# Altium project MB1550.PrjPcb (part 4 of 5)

## Sheet PMOD_STMOD+.SchDoc: PMOD & STMOD+
size A4; Date: Not used; ApprovedBy: Not used; CheckedBy: Not used; Author: Not used; CompanyName: STMicroelectronics; DrawnBy: Not used; Engineer: Not used; Organization: Not used; Address1: Not used; Address2: Not used; Address3: Not used; Address4: Not used; DocumentNumber: 19; Revision: Not used; SheetNumber: 19; SheetTotal: 24
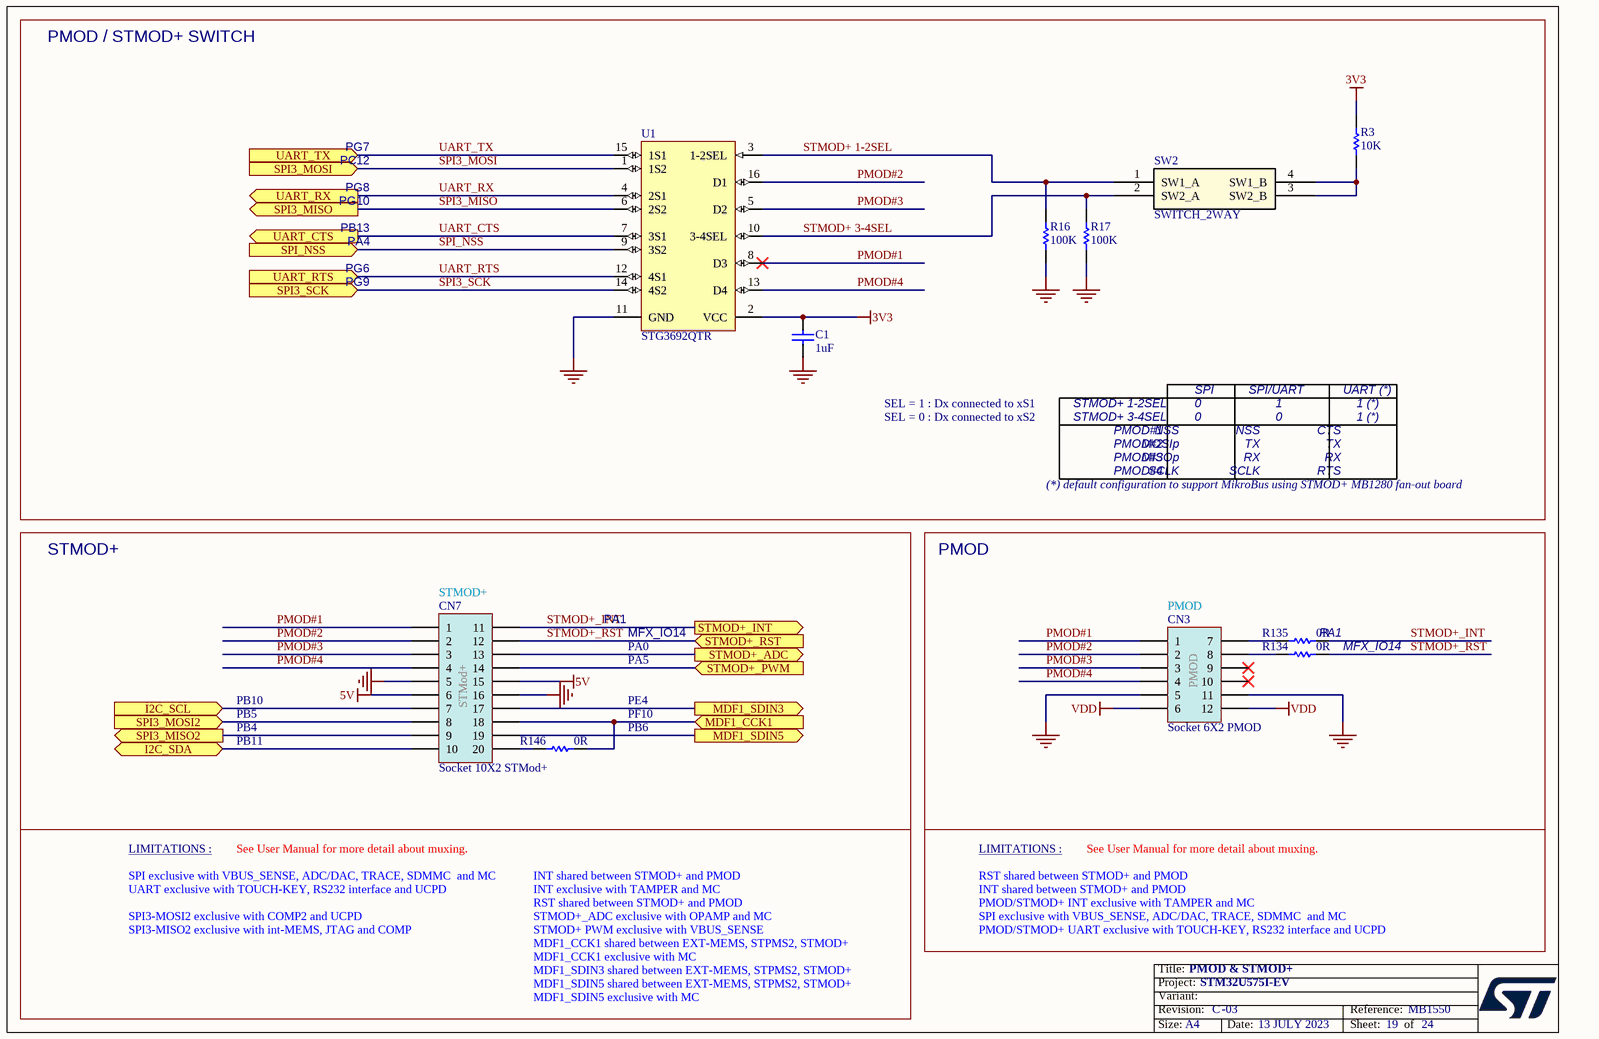
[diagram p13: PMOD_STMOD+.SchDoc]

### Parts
C1  value 1uF  [C0603]  (hidden comment: Capacitor)
CN3  Socket 6X2 PMOD  [CON_SAMTEC_SSW-106-02-F-D-RA__PMOD]
CN7  Socket 10X2 STMod+  [CON_SAMTEC_SQT-110-01-F-D-RA__STMOD+]
R3  value 10K  [R0603]  (hidden comment: Resistor)
R16  value 100K  [R0603]
R17  value 100K  [R0603]
R134  value 0R  [R0603]
R135  value 0R  [R0603]
R146  value 0R  [R0603]
SW2  SWITCH_2WAY  [SWI_C&K_SDA02H1SBD_2POS]
U1  STG3692QTR  [ICC_UFQFN16-EPAD_2P6X1P8_P040]

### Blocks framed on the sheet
PMOD / STMOD+ SWITCH: C1 R3 R16 R17 SW2 U1
STMOD+: CN7 R146
PMOD: CN3 R134 R135

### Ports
I2C_SCL (in), I2C_SDA (bidir), MDF1_CCK1 (in), MDF1_SDIN3 (out), MDF1_SDIN5 (out), SPI3_MISO2 (out), SPI3_MISO (out), SPI3_MOSI2 (in), SPI3_MOSI (in), SPI3_SCK (in), SPI_NSS (in), STMOD+_ADC (out), STMOD+_INT (out), STMOD+_PWM (in), STMOD+_RST (in), UART_CTS (out), UART_RTS (in), UART_RX (out), UART_TX (in)

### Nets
3V3: C1.2 R3.2 U1.2(VCC)
5V: CN7.6 CN7.15
GND: C1.1 CN3.5 CN3.11 CN7.5 CN7.16 R16.1 R17.1 U1.11(GND)
VDD: CN3.6 CN3.12
I2C_SCL: CN7.7 ; port I2C_SCL
I2C_SDA: CN7.10 ; port I2C_SDA
MDF1_CCK1: CN7.18 R146.1 ; port MDF1_CCK1
MDF1_SDIN3: CN7.17 ; port MDF1_SDIN3
MDF1_SDIN5: CN7.19 ; port MDF1_SDIN5
PMOD#1: CN3.1 CN7.1 U1.8(D3)
PMOD#2: CN3.2 CN7.2 U1.16(D1)
PMOD#3: CN3.3 CN7.3 U1.5(D2)
PMOD#4: CN3.4 CN7.4 U1.13(D4)
SPI3_MISO: U1.6(2S2) ; port SPI3_MISO
SPI3_MISO2: CN7.9 ; port SPI3_MISO2
SPI3_MOSI: U1.1(1S2) ; port SPI3_MOSI
SPI3_MOSI2: CN7.8 ; port SPI3_MOSI2
SPI3_SCK: U1.14(4S2) ; port SPI3_SCK
SPI_NSS: U1.9(3S2) ; port SPI_NSS
STMOD+ 1-2SEL: R16.2 SW2.1(SW1_A) U1.3(1-2SEL)
STMOD+ 3-4SEL: R17.2 SW2.2(SW2_A) U1.10(3-4SEL)
STMOD+_ADC: CN7.13 ; port STMOD+_ADC
STMOD+_INT: CN7.11 R135.2 ; port STMOD+_INT
STMOD+_PWM: CN7.14 ; port STMOD+_PWM
STMOD+_RST: CN7.12 R134.2 ; port STMOD+_RST
UART_CTS: U1.7(3S1) ; port UART_CTS
UART_RTS: U1.12(4S1) ; port UART_RTS
UART_RX: U1.4(2S1) ; port UART_RX
UART_TX: U1.15(1S1) ; port UART_TX
NetCN3_7: CN3.7 R135.1
NetCN3_8: CN3.8 R134.1
NetCN7_20: CN7.20 R146.2
NetR3_1: R3.1 SW2.3(SW2_B) SW2.4(SW1_B)

Not connected (* = marked no-connect by the designer): CN3 9* 10*

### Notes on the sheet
- PG7
- PC12
- PB13
- PG8
- PG10
- PA4
- PG9
- PG6
- SEL = 0 : Dx connected to xS2
- SEL = 1 : Dx connected to xS1
- STMOD+ 1-2SEL
- STMOD+ 3-4SEL
- PMOD#2
- PMOD#1
- MOSIp
- NSS
- 0
- SPI
- SPI/UART
- TX
- 1
- UART (*)
- CTS
- 1 (*)
- (*) default configuration to support MikroBus using STMOD+ MB1280 fan-out board
- PMOD#3
- PMOD#4
- MISOp
- SCLK
- RX
- RTS
- (near CN7) STMOD+
- PA0
- MFX_IO14
- PA1
- (near CN3) PMOD
- PB10
- PB5
- PA5
- PE4
- PF10
- PB11
- PB4
- PB6
- LIMITATIONS :
- See User Manual for more detail about muxing.
- SPI3-MOSI2 exclusive with COMP2 and UCPD
- UART exclusive with TOUCH-KEY, RS232 interface and UCPD
- SPI exclusive with VBUS_SENSE, ADC/DAC, TRACE, SDMMC  and MC
- RST shared between STMOD+ and PMOD
- INT shared between STMOD+ and PMOD
- INT exclusive with TAMPER and MC
- STMOD+_ADC exclusive with OPAMP and MC
- PMOD/STMOD+ INT exclusive with TAMPER and MC
- SPI3-MISO2 exclusive with int-MEMS, JTAG and COMP
- MDF1_CCK1 shared between EXT-MEMS, STPMS2, STMOD+
- MDF1_CCK1 exclusive with MC
- MDF1_SDIN3 shared between EXT-MEMS, STPMS2, STMOD+
- MDF1_SDIN5 shared between EXT-MEMS, STPMS2, STMOD+
- STMOD+ PWM exclusive with VBUS_SENSE
- PMOD/STMOD+ UART exclusive with TOUCH-KEY, RS232 interface and UCPD
- MDF1_SDIN5 exclusive with MC

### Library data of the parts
C1 = MCD-00010: Capacitor, MLCC, 1uF, 16V, X5R, 10%, 0603, T=0,8mm; Manufacturer_Part_Number: CC0603KRX5R7BB105; Manufacturer: YAGEO; Provided_By: SUBCO; Initial_Board_Reference: MB1274; Item Type: Item; Path: ws/MCD_ApplicationBoards/Lists/MCDPARTSdatabase
CN3 = MCD-00308: Socket, 6x2, 2.54mm, TH, RA, Height 8.51mm/7.62mm; Part_Type: Connector; Manufacturer_Part_Number: SSW-106-02-F-D-RA; Manufacturer: SAMTEC; Provided_By: SUBCO
CN7 = MCD-00309: Socket 10x2, 2.00mm, RA, TH, Height 6.35mm/2.29mm; Part_Type: Connector; Manufacturer_Part_Number: SQT-110-01-F-D-RA; Manufacturer: SAMTEC; Alternate_Manufacturer_Part_Number: FH200020C-12300;CNT-F200-2*10-GD-635/2.3; Alternate_Manufacturer: JIUBABA;CONNECT; Provided_By: SUBCO
R3 = MCD-00220: Resistor,10K,0603,1%,1/10W; Manufacturer_Part_Number: RC0603FR-0710KL; Manufacturer: YAGEO; Provided_By: SUBCO
R16 R17 = MCD-00223: Resistor,100K,0603,1%,1/10W; Manufacturer_Part_Number: RC0603FR-07100KL; Manufacturer: YAGEO; Provided_By: Subcon; Initial_Board_Reference: MB1319
R134 R135 R146 = MCD-00056: Resistor,0R,0603,5%,1/10W; Manufacturer_Part_Number: RC0603JR-070RL; Manufacturer: YAGEO; Provided_By: subcon; Initial_Board_Reference: MB1274
SW2 = MCD-00658: Dip Switch ,2Position ,Surface Mount Slide (Standard) ,2.54 pitch,25mA 24VDC; Part_Type: Misc; Manufacturer_Part_Number: SDA02H1SBD; Manufacturer: C&K; Provided_By: SUBCO
U1 = MCD-00317: Low voltage high bandwidth quad SPDT switch; Part_Type: IC; Manufacturer: STMICROELECTRONICS; BMS_Part_Number: 9159018; ECCN_US: EAR99; ECCN_EU: NEC; Provided_By: SUBCO with ST control

## Sheet SDCARD.SchDoc: SDCARD
size A4; Date: Not used; ApprovedBy: Not used; CheckedBy: Not used; Author: Not used; CompanyName: STMicroelectronics; DrawnBy: Not used; Engineer: Not used; Organization: Not used; Address1: Not used; Address2: Not used; Address3: Not used; Address4: Not used; DocumentNumber: 10; Revision: Not used; SheetNumber: 10; SheetTotal: 24
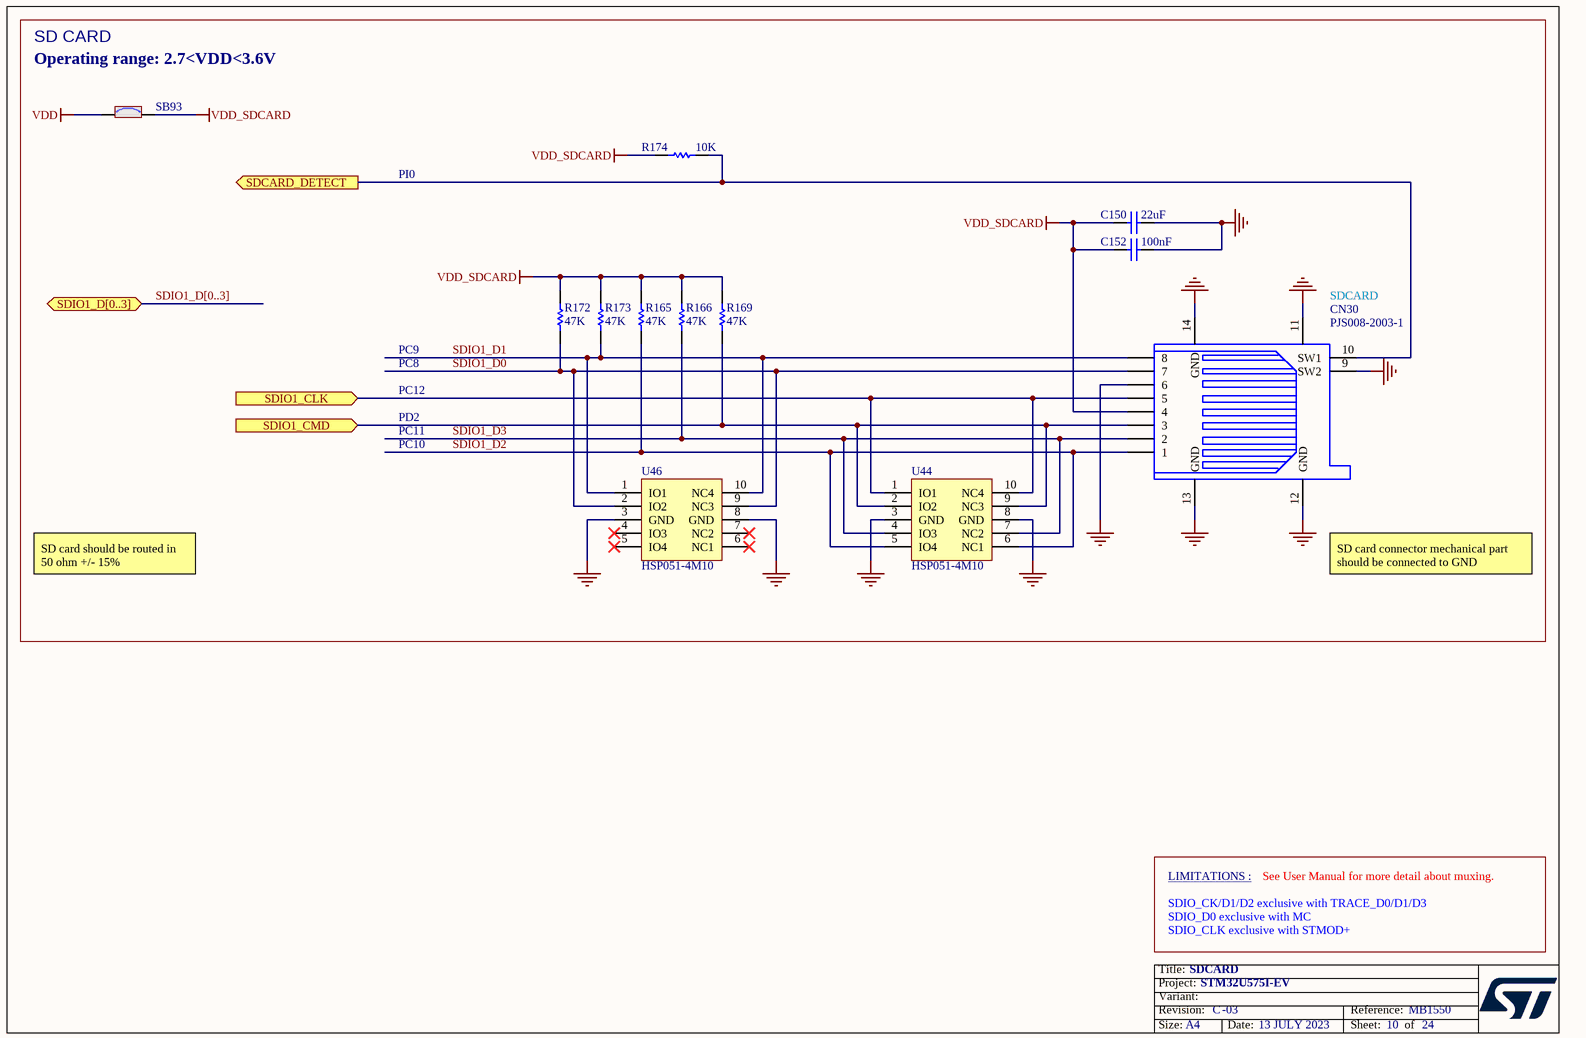
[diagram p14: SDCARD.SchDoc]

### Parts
C150  value 22uF  [C0603]
C152  value 100nF  [C0402]
CN30  value PJS008-2003-1  [CON_MICROSD_YAMAICHI_PJS008-2003-1]
R165  value 47K  [R0603]
R166  value 47K  [R0603]
R169  value 47K  [R0603]
R172  value 47K  [R0603]
R173  value 47K  [R0603]
R174  value 10K  [R0603]
SB93  (no value)  [SOLDER-BRIDGE_R0603-0R]
U44  value HSP051-4M10  [ESD_UQFN-10L_2P5X1_P050]
U46  value HSP051-4M10  [ESD_UQFN-10L_2P5X1_P050]

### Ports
SDCARD_DETECT (out), SDIO1_CLK (in), SDIO1_CMD (in), SDIO1_D[0..3] (bidir)

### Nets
GND: C150.2 C152.1 CN30.6 CN30.9(SW2) CN30.11(GND) CN30.12(GND) CN30.13(GND) CN30.14(GND) U44.3(GND) U44.8(GND) U46.3(GND) U46.8(GND)
VDD: SB93.1
VDD_SDCARD: C150.1 C152.2 CN30.4 R165.2 R166.2 R169.2 R172.2 R173.2 R174.2 SB93.2
SDCARD_DETECT: CN30.10(SW1) R174.1 ; port SDCARD_DETECT
SDIO1_CLK: CN30.5 U44.1(IO1) U44.10(NC4) ; port SDIO1_CLK
SDIO1_CMD: CN30.3 R169.1 U44.2(IO2) U44.9(NC3) ; port SDIO1_CMD
SDIO1_D0: CN30.7 R172.1 U46.2(IO2) U46.9(NC3)
SDIO1_D1: CN30.8 R173.1 U46.1(IO1) U46.10(NC4)
SDIO1_D2: CN30.1 R165.1 U44.5(IO4) U44.6(NC1)
SDIO1_D3: CN30.2 R166.1 U44.4(IO3) U44.7(NC2)

Not connected (* = marked no-connect by the designer): U46 4(IO3)* 5(IO4)* 6(NC1)* 7(NC2)*

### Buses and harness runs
bus SDIO1_D[0..3] = port SDIO1_D[0..3]

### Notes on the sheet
- SD CARD
- (near SB93) Operating range: 2.7<VDD<3.6V
- PI0
- (near CN30) SDCARD
- PC8
- PC9
- PC10
- PC11
- PD2
- PC12
- SD card should be routed in 50 ohm +/- 15%
- SD card connector mechanical part should be connected to GND
- LIMITATIONS :
- SDIO_CK/D1/D2 exclusive with TRACE_D0/D1/D3
- SDIO_D0 exclusive with MC
- See User Manual for more detail about muxing.
- SDIO_CLK exclusive with STMOD+

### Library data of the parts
C150 = MCD-00100: Capacitor, MLCC, 22uF, 6V3, X5R, 20%, 0603, T=0,8mm; Manufacturer_Part_Number: GRM188R60J226MEA0J; Manufacturer: MURATA; ECCN_US: EAR99; ECCN_EU: NEC; Provided_By: SUBCO
C152 = MCD-00006: Capacitor, MLCC, 100nF, 16V, X7R, 10%, 0402, T=0.5mm; Manufacturer_Part_Number: CC0402KRX7R7BB104; Manufacturer: YAGEO; Alternate_Manufacturer_Part_Number: GCM155R71C104KA55D; Alternate_Manufacturer: MURATA; Provided_By: SUBCO; ECCN_US: EAR99; ECCN_EU: NEC
CN30 = MCD-00023: MicroSD Card Conn, Reversed-Type, Mnt Push-Push, Positionning holes; Manufacturer: YAMAICHI; Part_Type: Connector; Provided_By: Subcon; Initial_Board_Reference: MB1274
R165 R166 R169 R172 R173 = MCD-00222: Resistor,47K,0603,1%,1/10W; Manufacturer_Part_Number: RC0603FR-0747KL; Manufacturer: YAGEO; Provided_By: Subcon; Initial_Board_Reference: MB1319
R174 = MCD-00220: Resistor,10K,0603,1%,1/10W; Manufacturer_Part_Number: RC0603FR-0710KL; Manufacturer: YAGEO; Provided_By: Subcon; Initial_Board_Reference: MB1319
SB93 = MCD-00071: Solder Bridge ON; Part_Type: Mechanical; Provided_By: Subcon; Initial_Board_Reference: MB1274
U44 U46 = MCD-00667: 4-line ESD protection for high speed lines; Part_Type: Diode; Manufacturer: STMICROELECTRONICS; BMS_Part_Number: 9179041; ECCN_US: EAR99; ECCN_EU: NEC; Provided_By: SUBCO with ST control

## Sheet SMARTCARD.SchDoc: SMARTCARD
size A4; Date: Not used; ApprovedBy: Not used; CheckedBy: Not used; Author: Not used; CompanyName: STMicroelectronics; DrawnBy: Not used; Engineer: Not used; Organization: Not used; Address1: Not used; Address2: Not used; Address3: Not used; Address4: Not used; DocumentNumber: 13; Revision: Not used; SheetNumber: 13; SheetTotal: 24
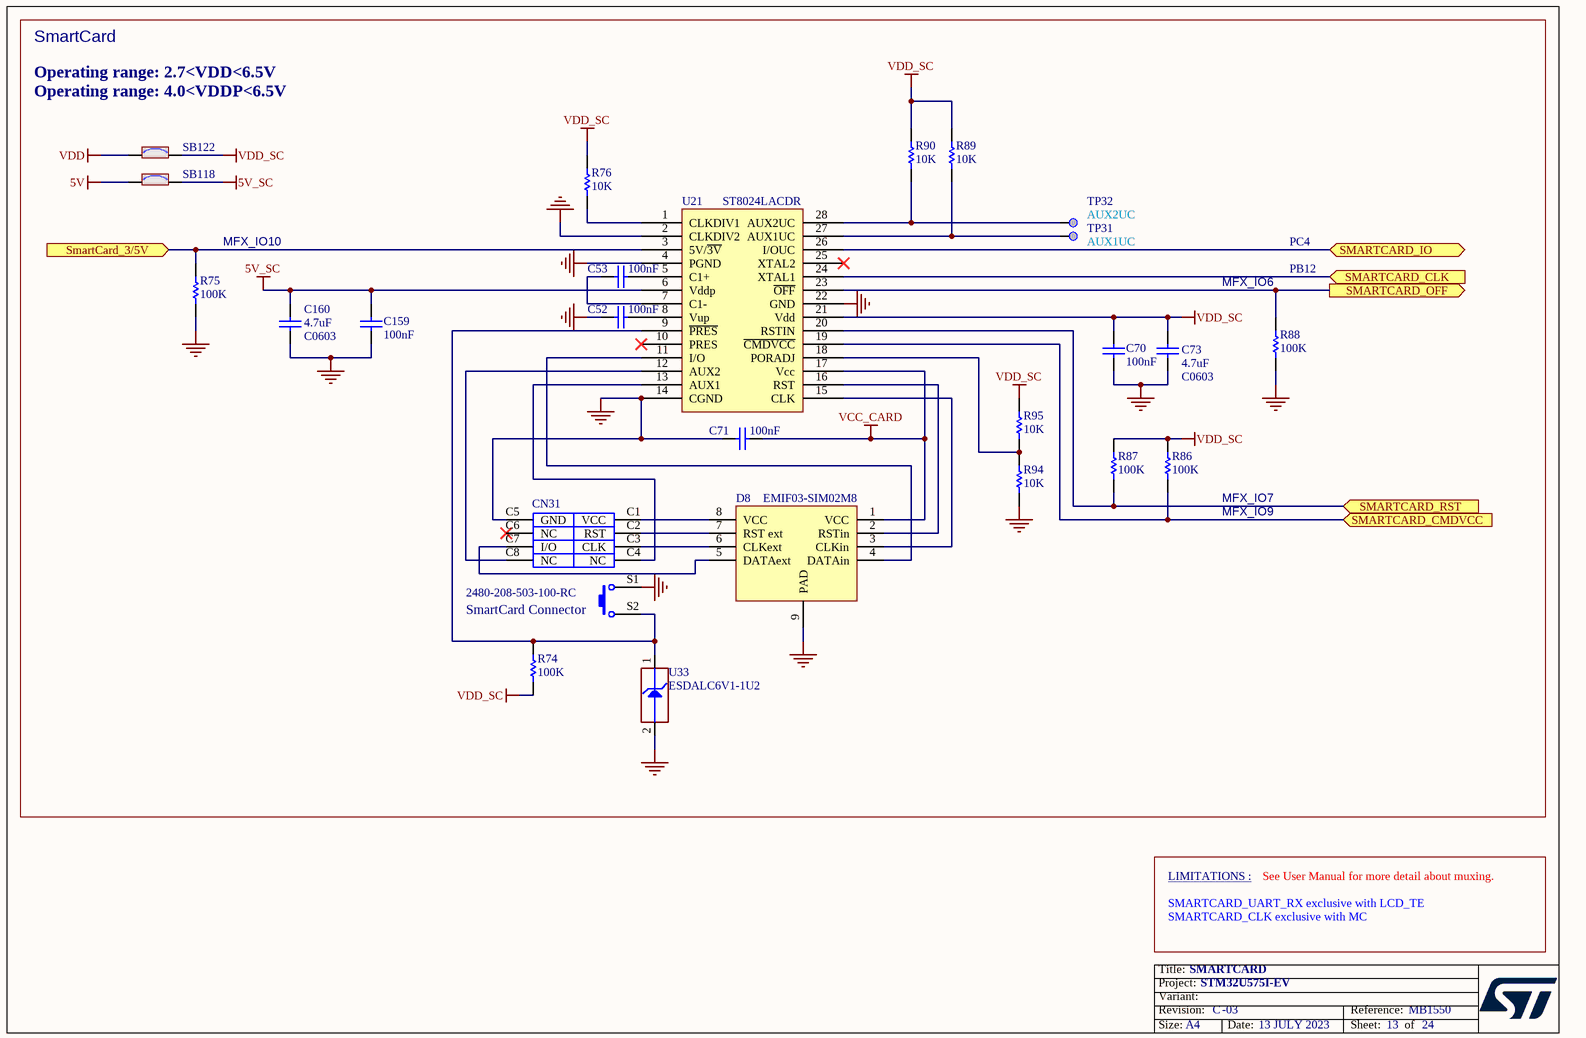
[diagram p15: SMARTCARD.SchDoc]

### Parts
C52  value 100nF  [C0402]
C53  value 100nF  [C0402]
C70  value 100nF  [C0402]
C71  value 100nF  [C0402]
C73  value 4.7uF  [C0603]
C159  value 100nF  [C0402]
C160  value 4.7uF  [C0603]
CN31  value 2480-208-503-100-RC  [CON_CARD-SOCKET_GUANG-LIAN-WEI_2480-208-503-100-RC]
D8  EMIF03-SIM02M8  [ESD_UQFN8-EPAD_1P7X1P5_P040]
R74  value 100K  [R0603]
R75  value 100K  [R0603]
R76  value 10K  [R0603]
R86  value 100K  [R0603]
R87  value 100K  [R0603]
R88  value 100K  [R0603]
R89  value 10K  [R0603]
R90  value 10K  [R0603]
R94  value 10K  [R0603]
R95  value 10K  [R0603]
SB118  (no value)  [SOLDER-BRIDGE_R0603-0R]
SB122  (no value)  [SOLDER-BRIDGE_R0603-0R]
TP31  value AUX1UC  [TP_SMD_1MM]  (no BOM)
TP32  value AUX2UC  [TP_SMD_1MM]  (no BOM)
U21  value ST8024LACDR  [ICC_SO28_18P10X7P60_P127]
U33  value ESDALC6V1-1U2  [ESD_ST0201]  (hidden comment: ESD-TRANSIL)

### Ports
SmartCard_3/5V (in), SMARTCARD_CLK (in), SMARTCARD_CMDVCC (in), SMARTCARD_IO (bidir), SMARTCARD_OFF (out), SMARTCARD_RST (in)

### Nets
5V: SB118.1
5V_SC: C159.1 C160.2 SB118.2 U21.6(Vddp)
GND: C52.2 C70.2 C71.2 C73.1 C159.2 C160.1 CN31.C5(GND) CN31.S1 D8.9(PAD) R75.1 R88.1 R94.1 U21.2(CLKDIV2) U21.4(PGND) U21.14(CGND) U21.22(GND) U33.2(GND)
VCC_CARD: C71.1 D8.1(VCC) U21.17(Vcc)
VDD: SB122.1
VDD_SC: C70.1 C73.2 R74.2 R76.2 R86.2 R87.2 R89.2 R90.2 R95.2 SB122.2 U21.21(Vdd)
SmartCard_3/5V: R75.2 U21.3(5V/~{3V}) ; port SmartCard_3/5V
SMARTCARD_CLK: U21.24(XTAL1) ; port SMARTCARD_CLK
SMARTCARD_CMDVCC: R86.1 U21.19(~{CMDVCC}) ; port SMARTCARD_CMDVCC
SMARTCARD_IO: U21.26(I/OUC) ; port SMARTCARD_IO
SMARTCARD_OFF: R88.2 U21.23(~{OFF}) ; port SMARTCARD_OFF
SMARTCARD_RST: R87.1 U21.20(RSTIN) ; port SMARTCARD_RST
NetC52_1: C52.1 U21.8(Vup)
NetC53_1: C53.1 U21.5(C1+)
NetC53_2: C53.2 U21.7(C1-)
NetCN31_C1: CN31.C1(VCC) D8.8(VCC)
NetCN31_C2: CN31.C2(RST) D8.7(RST_ext)
NetCN31_C3: CN31.C3(CLK) D8.6(CLKext)
NetCN31_C4: CN31.C4(NC) U21.13(AUX1)
NetCN31_C7: CN31.C7(I/O) D8.5(DATAext)
NetCN31_C8: CN31.C8(NC) U21.12(AUX2)
NetCN31_S2: CN31.S2 R74.1 U21.9(~{PRES}) U33.1(IO1)
NetD8_2: D8.2(RSTin) U21.16(RST)
NetD8_3: D8.3(CLKin) U21.15(CLK)
NetD8_4: D8.4(DATAin) U21.11(I/O)
NetR76_1: R76.1 U21.1(CLKDIV1)
NetR89_1: R89.1 TP31.1 U21.27(AUX1UC)
NetR90_1: R90.1 TP32.1 U21.28(AUX2UC)
NetR94_2: R94.2 R95.1 U21.18(PORADJ)

Not connected (* = marked no-connect by the designer): CN31 C6(NC)*; U21 10(PRES)* 25(XTAL2)*

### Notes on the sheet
- SmartCard
- Operating range: 2.7<VDD<6.5V
  Operating range: 4.0<VDDP<6.5V
- (near R75) MFX_IO10
- PC4
- (near R88) MFX_IO6
- PB12
- MFX_IO9
- MFX_IO7
- (near CN31) SmartCard Connector
- LIMITATIONS :
- SMARTCARD_UART_RX exclusive with LCD_TE
- SMARTCARD_CLK exclusive with MC
- See User Manual for more detail about muxing.

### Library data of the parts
C52 C53 C70 C71 C159 = MCD-00006: as C152 on sheet SDCARD
C73 C160 = MCD-00009: Capacitor, MLCC, 4.7uF, 16V, X5R, 10%, 0603, T=0.8mm; Manufacturer_Part_Number: CC0603KRX5R7BB475; Manufacturer: YAGEO; ECCN_US: EAR99; ECCN_EU: NEC; Provided_By: SUBCO
CN31 = MCD-01175: IC Card Socket 8 pin, SMT Open for Smartcard; Part_Type: Connector; Manufacturer: GUANG LIAN WEI; Provided_By: Subcon; Initial_Board_Reference: MB1397; Remark: update with pad renaming.
D8 = MCD-01229: 3 line IPAD, EMI filter for SIM card applications; Part_Type: Diode; Manufacturer: STMICROELECTRONICS; Provided_By: STM; Initial_Board_Reference: MB1397
R74 R75 R86-R88 = MCD-00223: as R16 on sheet PMOD_STMOD+
R76 R89 R90 R94 R95 = MCD-00220: as R174 on sheet SDCARD
SB118 SB122 = MCD-00071: as SB93 on sheet SDCARD
TP31 TP32 = MCD-00074: Test Point 1mm; Part_Type: Mechanical; Initial_Board_Reference: MB1274
U21 = MCD-01162: Smartcard interfaces; Part_Type: IC; Manufacturer: STMICROELECTRONICS; ECCN_US: EAR99; ECCN_EU: NEC; Provided_By: STM; Initial_Board_Reference: MB1397; Remark: idem ST8024CTR
U33 = MCD-00170: ESD protection 6V1; Part_Type: Diode; Manufacturer: STMICROELECTRONICS; ECCN_US: EAR99; ECCN_EU: NEC; Provided_By: Subcon; Initial_Board_Reference: MB1274

## Sheet SRAM.SchDoc: SRAM
size A4; Date: Not used; ApprovedBy: Not used; CheckedBy: Not used; Author: Not used; CompanyName: STMicroelectronics; DrawnBy: Not used; Engineer: Not used; Organization: Not used; Address1: Not used; Address2: Not used; Address3: Not used; Address4: Not used; DocumentNumber: 8; Revision: Not used; SheetNumber: 8; SheetTotal: 24
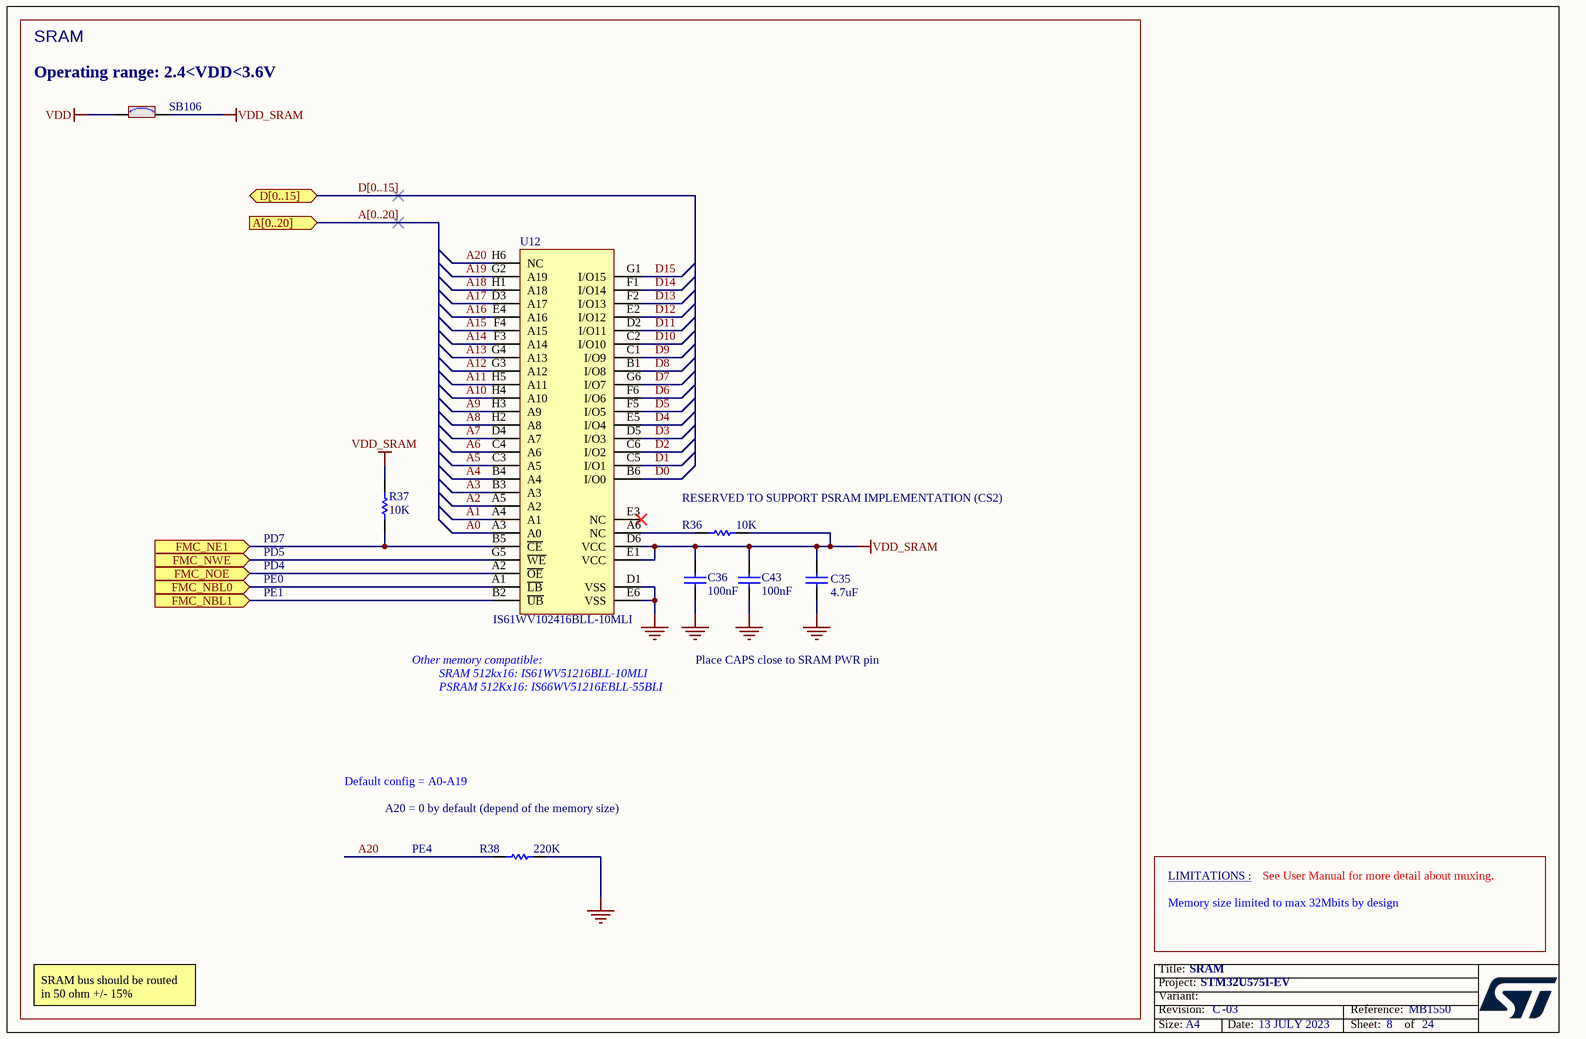
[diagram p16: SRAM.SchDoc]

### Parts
C35  value 4.7uF  [C0603]
C36  value 100nF  [C0402]
C43  value 100nF  [C0402]
R36  value 10K  [R0603]
R37  value 10K  [R0603]
R38  value 220K  [R0603]
SB106  (no value)  [SOLDER-BRIDGE_R0603-0R]
U12  value IS61WV102416BLL-10MLI  [ICC_MINI-BGA48_9X11_P075]

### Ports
A[0..20] (in), D[0..15] (bidir), FMC_NBL0 (in), FMC_NBL1 (in), FMC_NE1 (in), FMC_NOE (in), FMC_NWE (in)

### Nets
GND: C35.1 C36.1 C43.1 R38.2 U12.D1(VSS) U12.E6(VSS)
VDD: SB106.1
VDD_SRAM: C35.2 C36.2 C43.2 R36.1 R37.2 SB106.2 U12.D6(VCC) U12.E1(VCC)
A0: U12.A3(A0)
A1: U12.A4(A1)
A2: U12.A5(A2)
A3: U12.B3(A3)
A4: U12.B4(A4)
A5: U12.C3(A5)
A6: U12.C4(A6)
A7: U12.D4(A7)
A8: U12.H2(A8)
A9: U12.H3(A9)
A10: U12.H4(A10)
A11: U12.H5(A11)
A12: U12.G3(A12)
A13: U12.G4(A13)
A14: U12.F3(A14)
A15: U12.F4(A15)
A16: U12.E4(A16)
A17: U12.D3(A17)
A18: U12.H1(A18)
A19: U12.G2(A19)
A20: R38.1 U12.H6(NC)
D0: U12.B6(I/O0)
D1: U12.C5(I/O1)
D2: U12.C6(I/O2)
D3: U12.D5(I/O3)
D4: U12.E5(I/O4)
D5: U12.F5(I/O5)
D6: U12.F6(I/O6)
D7: U12.G6(I/O7)
D8: U12.B1(I/O8)
D9: U12.C1(I/O9)
D10: U12.C2(I/O10)
D11: U12.D2(I/O11)
D12: U12.E2(I/O12)
D13: U12.F2(I/O13)
D14: U12.F1(I/O14)
D15: U12.G1(I/O15)
FMC_NBL0: U12.A1(~{LB}) ; port FMC_NBL0
FMC_NBL1: U12.B2(~{UB}) ; port FMC_NBL1
FMC_NE1: R37.1 U12.B5(~{CE}) ; port FMC_NE1
FMC_NOE: U12.A2(~{OE}) ; port FMC_NOE
FMC_NWE: U12.G5(~{WE}) ; port FMC_NWE
NetR36_2: R36.2 U12.A6(NC)

Not connected (* = marked no-connect by the designer): U12 E3(NC)*

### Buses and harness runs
bus A[0..20] = port A[0..20]
bus D[0..15] = port D[0..15]

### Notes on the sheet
- SRAM
- (near SB106) Operating range: 2.4<VDD<3.6V
- (near R36) RESERVED TO SUPPORT PSRAM IMPLEMENTATION (CS2)
- PE0
- PD7
- PD5
- PD4
- PE1
- Other memory compatible:
- SRAM 512kx16: IS61WV51216BLL-10MLI
- PSRAM 512Kx16: IS66WV51216EBLL-55BLI
- Place CAPS close to SRAM PWR pin
- Default config = A0-A19
- (near R38) A20 = 0 by default (depend of the memory size)
- PE4
- LIMITATIONS :
- Memory size limited to max 32Mbits by design
- See User Manual for more detail about muxing.
- SRAM bus should be routed in 50 ohm +/- 15%

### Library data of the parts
C35 = MCD-00009: as C73 on sheet SMARTCARD
C36 C43 = MCD-00006: as C152 on sheet SDCARD
R36 R37 = MCD-00220: as R174 on sheet SDCARD
R38 = MCD-00347: Resistor,220K,0603,1%,1/10W; Manufacturer_Part_Number: RC0603FR-07220KL; Manufacturer: YAGEO; Provided_By: Subcon
SB106 = MCD-00071: as SB93 on sheet SDCARD
U12 = MCD-00560: SRAM 16Mb 10ns 1Mx16 Async SRAM 3.3v; Manufacturer: ISSI; Part_Type: IC; Provided_By: Subcon; Initial_Board_Reference: MB1331

## Sheet USB_TYPEC.SchDoc: USB TYPE C
size A3; Date: Not used; ApprovedBy: Not used; CheckedBy: Not used; Author: Not used; CompanyName: STMicroelectronics; DrawnBy: Not used; Engineer: Not used; Organization: Not used; Address1: Not used; Address2: Not used; Address3: Not used; Address4: Not used; DocumentNumber: 12; Revision: Not used; SheetNumber: 12; SheetTotal: 24
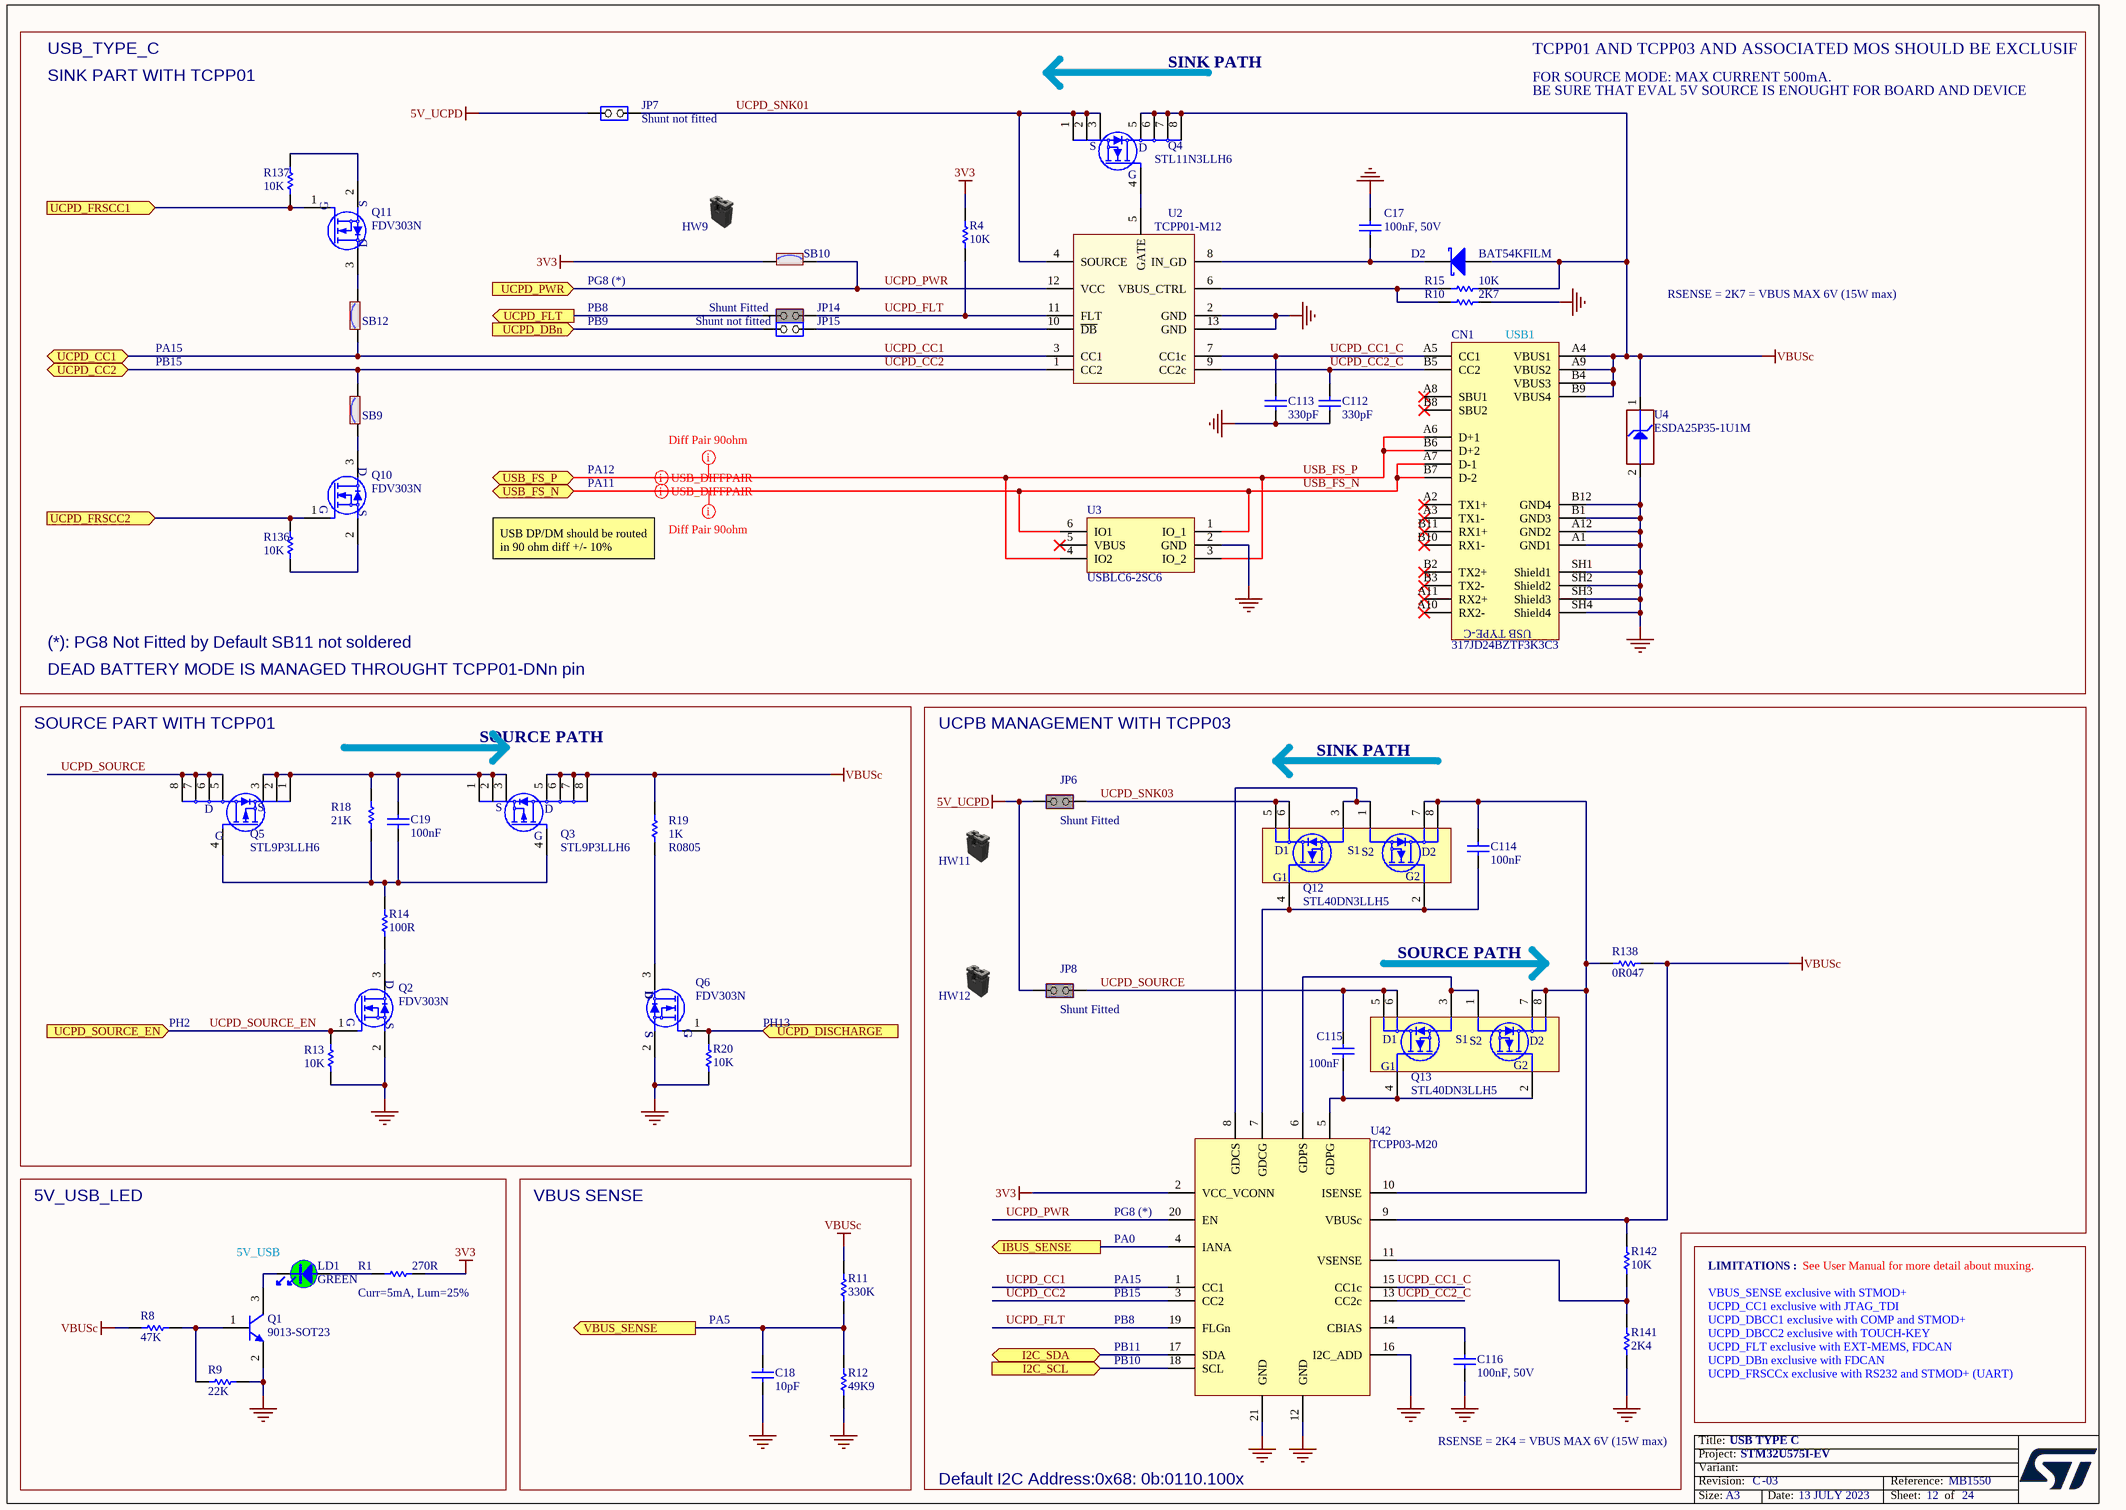
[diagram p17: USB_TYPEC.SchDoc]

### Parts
C17  value 100nF, 50V  [C0603]
C18  value 10pF  [C0402]
C19  value 100nF  [C0603]
C112  value 330pF  [C0402]  (hidden comment: Capacitor)
C113  value 330pF  [C0402]  (hidden comment: Capacitor)
C114  value 100nF  [C0603]
C115  value 100nF  [C0603]
C116  value 100nF, 50V  [C0603]
CN1  value 317JD24BZTF3K3C3  [CON_USB-TYPEC_COXOC_317JD24BZTF3K3C3]  (hidden comment: USB_TYPE_C_Receptacle_317JD24BZTF3K3C3)
D2  value BAT54KFILM  [DIO_SOD523_1A_2K]
HW9  (no value)  (mechanical)
HW11  (no value)  (mechanical)
HW12  (no value)  (mechanical)
JP6  value Shunt Fitted  [CON_SAMTEC_TSW-102-07-G-S]
JP7  value Shunt not fitted  [CON_SAMTEC_TSW-102-07-G-S]  (hidden comment: Jumper_Header 2x1)
JP8  value Shunt Fitted  [CON_SAMTEC_TSW-102-07-G-S]
JP14  value Shunt Fitted  [CON_SAMTEC_TSW-102-07-G-S]
JP15  value Shunt not fitted  [CON_SAMTEC_TSW-102-07-G-S]  (hidden comment: Jumper_Header 2x1)
LD1  value GREEN  [LED_0603_OSRAM_LG-Q396-PS-35_GREEN_1A2K_H0P4]
Q1  value 9013-SOT23  [NPN_SOT23]
Q2  value FDV303N  [MOS_SOT23]  (hidden comment: BSN20)
Q3  STL9P3LLH6  [MOS_POWERFLAT_3P3X3P3_P065]
Q4  value STL11N3LLH6  [MOS_POWERFLAT_3P3X3P3_P065]
Q5  STL9P3LLH6  [MOS_POWERFLAT_3P3X3P3_P065]
Q6  value FDV303N  [MOS_SOT23]  (hidden comment: BSN20)
Q10  value FDV303N  [MOS_SOT23]  (hidden comment: BSN20)
Q11  value FDV303N  [MOS_SOT23]  (hidden comment: BSN20)
Q12  STL40DN3LLH5  [PowerFLAT_5x6]
Q13  STL40DN3LLH5  [PowerFLAT_5x6]
R1  value 270R  [R0603]
R4  value 10K  [R0603]
R8  value 47K  [R0603]
R9  value 22K  [R0603]
R10  value 2K7  [R0603]
R11  value 330K  [R0603]
R12  value 49K9  [R0603]
R13  value 10K  [R0603]
R14  value 100R  [R0603]  (hidden comment: Resistor)
R15  value 10K  [R0603]
R18  value 21K  [R0603]
R19  value 1K  [R0805]
R20  value 10K  [R0603]
R136  value 10K  [R0603]
R137  value 10K  [R0603]
R138  value 0R047  [R0805_H0P5]  (hidden comment: Resistor)
R141  value 2K4  [R0603]  (hidden comment: Resistor)
R142  value 10K  [R0603]
SB9  (no value)  [SOLDER-BRIDGE_R0603-0R]
SB10  (no value)  [SOLDER-BRIDGE_R0603-0R]
SB12  (no value)  [SOLDER-BRIDGE_R0603-0R]
U2  value TCPP01-M12  [ICC_QFN12L-EPAD_3X3_P050]
U3  USBLC6-2SC6  [ESD_SOT23-6L]
U4  value ESDA25P35-1U1M  [ESD_QFN1610_2N_1K_2A]
U42  TCPP03-M20  [ICC_QFN20-EPAD_4X4_P050]

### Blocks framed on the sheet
5V_USB_LED: LD1 Q1 R1 R8 R9
VBUS SENSE: C18 R11 R12

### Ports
I2C_SCL (in), I2C_SDA (bidir), IBUS_SENSE (out), UCPD_CC1 (bidir), UCPD_CC2 (bidir), UCPD_DBn (in), UCPD_DISCHARGE (in), UCPD_FLT (out), UCPD_FRSCC1 (in), UCPD_FRSCC2 (in), UCPD_PWR (in), UCPD_SOURCE_EN (in), USB_FS_N (bidir), USB_FS_P (bidir), VBUS_SENSE (out)

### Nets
3V3: R1.2 R4.1 SB10.1 U42.2(VCC_VCONN)
5V_UCPD: JP6.1(COMMON) JP7.1(COMMON) JP8.1(COMMON)
GND: C17.2 C18.1 C112.1 C113.1 C116.2 CN1.A1(GND1) CN1.A12(GND2) CN1.B1(GND3) CN1.B12(GND4) CN1.SH1(Shield1) CN1.SH2(Shield2) CN1.SH3(Shield3) CN1.SH4(Shield4) Q1.2(E) Q2.2(S) Q6.2(S) R9.2 R10.2 R12.1 R13.1 R20.1 R141.1 U2.2(GND) U2.13(GND) U3.2(GND) U4.2(GND) U42.12(GND) U42.16(I2C_ADD) U42.21(GND)
VBUSc: CN1.A4(VBUS1) CN1.A9(VBUS2) CN1.B4(VBUS3) CN1.B9(VBUS4) D2.1(A) Q3.5(D) Q3.6(D) Q3.7(D) Q3.8(D) Q4.5(D) Q4.6(D) Q4.7(D) Q4.8(D) R8.1 R11.2 R15.2 R19.2 R138.1 R142.2 U4.1(IO1) U42.9(VBUSc)
I2C_SCL: U42.18(SCL) ; port I2C_SCL
I2C_SDA: U42.17(SDA) ; port I2C_SDA
IBUS_SENSE: U42.4(IANA) ; port IBUS_SENSE
PB8: JP14.1(COMMON) ; port UCPD_FLT
PB9: JP15.1(COMMON) ; port UCPD_DBn
UCPD_CC1: SB12.1 U2.3(CC1) U42.1(CC1) ; port UCPD_CC1
UCPD_CC1_C: C113.2 CN1.A5(CC1) U2.7(CC1c) U42.15(CC1c)
UCPD_CC2: SB9.2 U2.1(CC2) U42.3(CC2) ; port UCPD_CC2
UCPD_CC2_C: C112.2 CN1.B5(CC2) U2.9(CC2c) U42.13(CC2c)
UCPD_DISCHARGE: Q6.1(G) R20.2 ; port UCPD_DISCHARGE
UCPD_FLT: JP14.2(NO) R4.2 U2.11(FLT) U42.19(FLGn)
UCPD_FRSCC1: Q11.1(G) R137.1 ; port UCPD_FRSCC1
UCPD_FRSCC2: Q10.1(G) R136.2 ; port UCPD_FRSCC2
UCPD_PWR: SB10.2 U2.12(VCC) U42.20(EN) ; port UCPD_PWR
UCPD_SNK01: JP7.2(NO) Q4.1(S) Q4.2(S) Q4.3(S) U2.4(SOURCE)
UCPD_SNK03: JP6.2(NO) Q12.5(D1) Q12.6(D1)
UCPD_SOURCE: C115.2 JP8.2(NO) Q5.5(D) Q5.6(D) Q5.7(D) Q5.8(D) Q13.5(D1) Q13.6(D1)
UCPD_SOURCE_EN: Q2.1(G) R13.2 ; port UCPD_SOURCE_EN
USB_FS_N: CN1.A7(D-1) CN1.B7(D-2) U3.1(IO_1) U3.6(IO1) ; port USB_FS_N
USB_FS_P: CN1.A6(D+1) CN1.B6(D+2) U3.3(IO_2) U3.4(IO2) ; port USB_FS_P
VBUS_SENSE: C18.2 R11.1 R12.2 ; port VBUS_SENSE
NetC17_1: C17.1 D2.2(K) U2.8(IN_GD)
NetC19_1: C19.1 Q3.4(G) Q5.4(G) R14.2 R18.1
NetC19_2: C19.2 Q3.1(S) Q3.2(S) Q3.3(S) Q5.1(S) Q5.2(S) Q5.3(S) R18.2
NetC114_1: C114.1 Q12.2(G2) Q12.4(G1) U42.7(GDCG)
NetC114_2: C114.2 Q12.7(D2) Q12.8(D2) Q13.7(D2) Q13.8(D2) R138.2 U42.10(ISENSE)
NetC115_1: C115.1 Q13.2(G2) Q13.4(G1) U42.5(GDPG)
NetC116_1: C116.1 U42.14(CBIAS)
NetJP15_2: JP15.2(NO) U2.10(~{DB})
NetLD1_1: LD1.1 R1.1
NetLD1_2: LD1.2 Q1.3(C)
NetQ1_1: Q1.1(B) R8.2 R9.1
NetQ2_3: Q2.3(D) R14.1
NetQ4_4: Q4.4(G) U2.5(GATE)
NetQ6_3: Q6.3(D) R19.1
NetQ10_2: Q10.2(S) R136.1
NetQ10_3: Q10.3(D) SB9.1
NetQ11_2: Q11.2(S) R137.2
NetQ11_3: Q11.3(D) SB12.2
NetQ12_1: Q12.1(S2) Q12.3(S1) U42.8(GDCS)
NetQ13_1: Q13.1(S2) Q13.3(S1) U42.6(GDPS)
NetR10_1: R10.1 R15.1 U2.6(VBUS_CTRL)
NetR141_2: R141.2 R142.1 U42.11(VSENSE)

Not connected (* = marked no-connect by the designer): CN1 A2(TX1+)* A3(TX1-)* A8(SBU1)* A10(RX2-)* A11(RX2+)* B2(TX2+)* B3(TX2-)* B8(SBU2)* B10(RX1-)* B11(RX1+)*; U3 5(VBUS)*

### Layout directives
mark named Diff Pair 90ohm: USB_FS_N, USB_FS_P
differential pair: USB_FS_N, USB_FS_P

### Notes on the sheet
- USB_TYPE_C
- SINK PART WITH TCPP01
- SINK PATH
- FOR SOURCE MODE: MAX CURRENT 500mA.
- TCPP01 AND TCPP03 AND ASSOCIATED MOS SHOULD BE EXCLUSIF
- BE SURE THAT EVAL 5V SOURCE IS ENOUGHT FOR BOARD AND DEVICE
- PB8
- PG8 (*)
- RSENSE = 2K7 = VBUS MAX 6V (15W max)
- PA15
- PB15
- PB9
- (near CN1) USB1
- PA12
- PA11
- USB DP/DM should be routed in 90 ohm diff +/- 10%
- (*): PG8 Not Fitted by Default SB11 not soldered
- DEAD BATTERY MODE IS MANAGED THROUGHT TCPP01-DNn pin
- SOURCE PART WITH TCPP01
- SOURCE PATH
- UCPB MANAGEMENT WITH TCPP03
- PH2
- (near R20) PH13
- (near LD1) 5V_USB
- PA0
- (near U42) PG8 (*)
- (near R1) Curr=5mA, Lum=25%
- PA5
- LIMITATIONS :
- UCPD_CC1 exclusive with JTAG_TDI
- VBUS_SENSE exclusive with STMOD+
- UCPD_DBCC1 exclusive with COMP and STMOD+
- See User Manual for more detail about muxing.
- PB10
- PB11
- UCPD_FLT exclusive with EXT-MEMS, FDCAN
- UCPD_DBCC2 exclusive with TOUCH-KEY
- UCPD_DBn exclusive with FDCAN
- UCPD_FRSCCx exclusive with RS232 and STMOD+ (UART)
- RSENSE = 2K4 = VBUS MAX 6V (15W max)
- Default I2C Address:0x68: 0b:0110.100x

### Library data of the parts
C17 C116 = MCD-01099: Capacitor,100nF,50V,X7R,10%,0603; Manufacturer_Part_Number: CC0603KRX7R9BB104; Manufacturer: YAGEO; BMS_Part_Number: 9142278; Provided_By: SUBCO
C18 = MCD-00015: Capacitor, MLCC, 10pF, 50V, NPO, 5%, 0402, T=0,5mm; Manufacturer_Part_Number: CC0402JRNPO9BN100; Manufacturer: YAGEO; Provided_By: subcon; Initial_Board_Reference: MB1274
C19 C114 C115 = MCD-00211: Capacitor, MLCC, 100nF, 16V, X7R, 10%, 0603, T=0,8mm; Manufacturer_Part_Number: CC0603KRX7R7BB104; Manufacturer: YAGEO; Provided_By: Subcon; Initial_Board_Reference: MB1319
C112 C113 = MCD-01579: Capacitor, MLCC, 330pF, 50V, NPO, +/-5%, 0402, T=0,5mm; Manufacturer_Part_Number: CC0402JRNPO9BN331; Manufacturer: YAGEO; Part_Preference: Recommended
CN1 = MCD-01108: USB tyce C certified receptacle for 1.6mm pcb height; Part_Type: Connector; Manufacturer: CHANT SINCERE (COXOC); Provided_By: SUBCO
D2 = MCD-01677: Small signal Schottky diodes; Part_Type: Diode; Manufacturer: STMICROELECTRONICS; BMS_Part_Number: 9151123; ECCN_US: EAR99; ECCN_EU: NEC; Provided_By: SUBCO
HW9 HW11 HW12 = MCD-00043: SHUNT 2.54mm BLACK; Manufacturer_Part_Number: SNT-100-BK-G; Manufacturer: SAMTEC; Part_Type: Mechanical; Provided_By: Subcon; Initial_Board_Reference: MB1274
JP6 JP8 JP14 = MCD-00683: Header, 2x1, 2,54mm, VR, TH, Height 5.84mm/2.54mm - Shunt Fitted by default; Part_Type: Connector; Manufacturer_Part_Number: TSW-102-07-x-S; Manufacturer: SAMTEC; Provided_By: Subcon; Initial_Board_Reference: MB1331
JP7 JP15 = MCD-00045: Header, 2x1, 2,54mm, VR, TH, Height 5.84mm/2.54mm; Part_Type: Connector; Manufacturer_Part_Number: TSW-102-07-x-S; Manufacturer: SAMTEC; Provided_By: Subcon; Initial_Board_Reference: MB1274; Remark: 3D KO: BZ: 40098
LD1 = MCD-00588: LED Green, 0603 SMD, Forward Voltage Typ=2V, Max=2.5V; Part_Type: Display; Manufacturer_Part_Number: LG Q396-PS-35; Manufacturer: OSRAM OPTO SEMICONDUCTORS; Alternate_Manufacturer_Part_Number: VLMTG1300-GS08; Alternate_Manufacturer: VISHAY SEMICONDUCTOR OPTO DIVISION; Provided_By: Subcon; Initial_Board_Reference: MB1331
Q1 = MCD-00073: NPN Bipolar Transistor; Part_Type: IC; Manufacturer_Part_Number: BSR14; Manufacturer: NXP; ECCN_US: EAR99; ECCN_EU: NEC; Provided_By: Subcon; Initial_Board_Reference: MB1274
Q2 Q6 Q10 Q11 = MCD-01164: N-channel Digital FET; Part_Type: IC; Manufacturer: FAIRCHILD; BMS_Part_Number: 9153036; Provided_By: SUBCO
Q3 Q5 = MCD-01126: Power Mosfet, P-channel,VDS -30V,RDS 12mohm typ,ID -9A; Part_Type: IC; Manufacturer: STMICROELECTRONICS; BMS_Part_Number: 9153557; ECCN_US: EAR99; ECCN_EU: NEC; Provided_By: SUBCO with ST control
Q4 = MCD-01810: N-channel 30 V, 6 mΩ typ, 11 A STripFET™ H6, Power MOSFET in a PowerFLAT™ 3.3x3.3 package; Part_Type: IC; Manufacturer: STMICROELECTRONICS; BMS_Part_Number: 9153561; ECCN_US: EAR99; ECCN_EU: NEC; Provided_By: SUBCO with ST control
Q12 Q13 = MCD-02152: Dual N-channel 30 V, 0.016 Ω typ., 40 A, STripFET™ H5 Power MOSFET; Part_Type: Transistor; Manufacturer: STMICROELECTRONICS; ECCN_US: EAR99; ECCN_EU: NEC; Provided_By: SUBCO
R1 = MCD-00442: Resistor,270R,0603,1%,1/10W; Manufacturer_Part_Number: RC0603FR-07270RL; Manufacturer: YAGEO; Provided_By: Subcon
R4 R13 R15 R20 R136 R137 R142 = MCD-00220: as R174 on sheet SDCARD
R8 = MCD-00222: as R165 on sheet SDCARD
R9 = MCD-00430: Resistor,22K,0603,1%,1/10W; Manufacturer_Part_Number: RC0603FR-0722KL; Manufacturer: YAGEO; Provided_By: Subcon
R10 = MCD-00218: Resistor,2K7,0603,1%,1/10W; Manufacturer_Part_Number: RC0603FR-072K7L; Manufacturer: YAGEO; Provided_By: Subcon; Initial_Board_Reference: MB1319
R11 = MCD-00458: Resistor,330K,0603,1%,1/10W; Manufacturer_Part_Number: RC0603FR-07330KL; Manufacturer: YAGEO; Provided_By: Subcon
R12 = MCD-01171: Resistor,49K9,0603,1%; Manufacturer_Part_Number: RC0603FR-0749K9L; Manufacturer: YAGEO; Provided_By: Subcon; Initial_Board_Reference: MB1397
R14 = MCD-00224: Resistor,100R,0603,1%,1/10W; Manufacturer_Part_Number: RC0603FR-07100RL; Manufacturer: YAGEO; ECCN_US: EAR99; ECCN_EU: NEC; Provided_By: SUBCO
R18 = MCD-01189: Resistor,21K,0603,1%,1/10W; Manufacturer_Part_Number: RC0603FR-0721KL; Manufacturer: YAGEO; ECCN_US: EAR99; ECCN_EU: NEC; Provided_By: SUBCO
R19 = MCD-01578: Resistor, 1K, 0805, 1%, 1/8W; Manufacturer_Part_Number: RC0805FR-071KL; Manufacturer: YAGEO; ECCN_US: EAR99; ECCN_EU: NEC; Provided_By: SUBCO
R138 = MCD-02151: Current Detection Resistor, 0R047, 0805, 1%, 1/4W; Manufacturer_Part_Number: RL0805FR-7W0R047L; Manufacturer: YAGEO; ECCN_US: NEC; ECCN_EU: EAR99; Provided_By: SUBCO
R141 = MCD-00434: Resistor,2K4,0603,1%,1/10W; Manufacturer_Part_Number: RC0603FR-072K4L; Manufacturer: YAGEO; Part_Preference: Recommended
SB9 SB10 SB12 = MCD-00071: as SB93 on sheet SDCARD
U2 = MCD-01809: USB Type-C Port Protection for USB Power Delivery, PPS compliant; Part_Type: IC; Manufacturer: STMICROELECTRONICS; BMS_Part_Number: 9151145; ECCN_US: EAR99; ECCN_EU: NEC; Provided_By: SUBCO with ST control
U3 = MCD-00163: Very low capacitance ESD protection; Part_Type: IC; Manufacturer: STMICROELECTRONICS; BMS_Part_Number: 9151075; ECCN_US: EAR99; ECCN_EU: NEC; Provided_By: SUBCO with ST control
U4 = MCD-01207: High power Transient voltage suppressor:25V/35A EOS and ESD transients protection.; Part_Type: Diode; Manufacturer: STMICROELECTRONICS; BMS_Part_Number: 9179045; ECCN_US: EAR99; ECCN_EU: NEC; Provided_By: SUBCO with ST control
U42 = MCD-02130: USB Type-C Port Protection for USB DRP Power Delivery, PPS compliant; Part_Type: IC; Manufacturer: STMICROELECTRONICS; ECCN_US: EAR99; ECCN_EU: NEC; Provided_By: SUBCO with ST control

## Sheet LCD_TFT_320x240.SchDoc: LCD TFT 320x240
size A4; Date: Not used; ApprovedBy: Not used; CheckedBy: Not used; Author: Not used; CompanyName: STMicroelectronics; DrawnBy: Not used; Engineer: Not used; Organization: Not used; Address1: Not used; Address2: Not used; Address3: Not used; Address4: Not used; DocumentNumber: 7; Revision: Not used; SheetNumber: 7; SheetTotal: 24
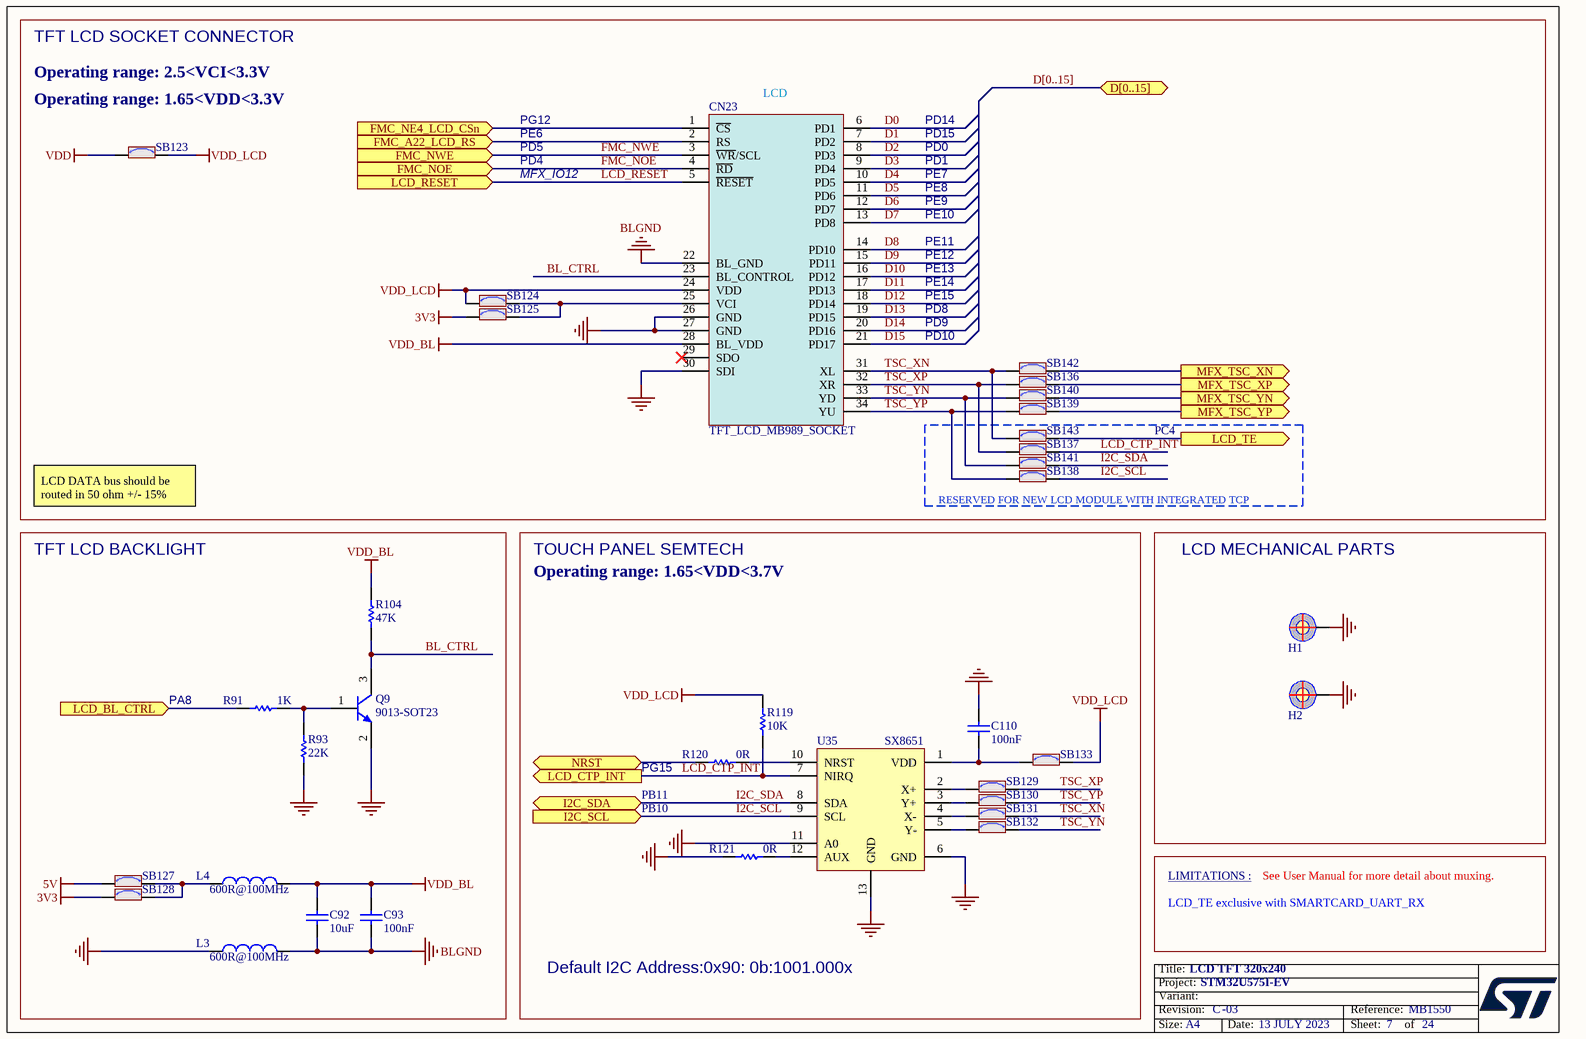
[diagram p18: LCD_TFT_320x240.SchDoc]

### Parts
C92  value 10uF  [C0805]
C93  value 100nF  [C0402]
C110  value 100nF  [C0402]
CN23  value TFT_LCD_MB989_SOCKET  [CON_SAMTEC_SSW-117-21-X-D_INV]
H1  (no value)  [PTH_M1261-3005-N_3P5X6_M3_H14]  (no BOM)
H2  (no value)  [PTH_M1261-3005-N_3P5X6_M3_H14]  (no BOM)
L3  value 600R@100MHz  [L0603]
L4  value 600R@100MHz  [L0603]
Q9  value 9013-SOT23  [NPN_SOT23]
R91  value 1K  [R0603]
R93  value 22K  [R0603]
R104  value 47K  [R0603]
R119  value 10K  [R0603]
R120  value 0R  [R0603]
R121  value 0R  [R0603]
SB123  (no value)  [SOLDER-BRIDGE_R0603-0R]
SB124  (no value)  [SOLDER-BRIDGE_R0603-0R]
SB125  (no value)  [SOLDER-BRIDGE_R0603-0R]
SB127  (no value)  [SOLDER-BRIDGE_R0603-0R]
SB128  (no value)  [SOLDER-BRIDGE_R0603-0R]
SB129  (no value)  [SOLDER-BRIDGE_R0603-0R]
SB130  (no value)  [SOLDER-BRIDGE_R0603-0R]
SB131  (no value)  [SOLDER-BRIDGE_R0603-0R]
SB132  (no value)  [SOLDER-BRIDGE_R0603-0R]
SB133  (no value)  [SOLDER-BRIDGE_R0603-0R]
SB136  (no value)  [SOLDER-BRIDGE_R0603-0R]
SB137  (no value)  [SOLDER-BRIDGE_R0603-0R]
SB138  (no value)  [SOLDER-BRIDGE_R0603-0R]
SB139  (no value)  [SOLDER-BRIDGE_R0603-0R]
SB140  (no value)  [SOLDER-BRIDGE_R0603-0R]
SB141  (no value)  [SOLDER-BRIDGE_R0603-0R]
SB142  (no value)  [SOLDER-BRIDGE_R0603-0R]
SB143  (no value)  [SOLDER-BRIDGE_R0603-0R]
U35  SX8651  [ICC_DFN12-EPAD_3X3_P045]

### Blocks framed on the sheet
TFT LCD SOCKET CONNECTOR: CN23 SB123-SB125 SB136 SB139 SB140 SB142
PC4: SB137 SB138 SB141 SB143
TFT LCD BACKLIGHT: C92 C93 L3 L4 Q9 R91 R93 R104 SB127 SB128
LCD MECHANICAL PARTS: H1 H2

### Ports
D[0..15] (bidir), FMC_A22_LCD_RS (in), FMC_NE4_LCD_CSn (in), FMC_NOE (in), FMC_NWE (in), I2C_SCL (in), I2C_SDA (bidir), LCD_BL_CTRL (in), LCD_CTP_INT (out), LCD_RESET (in), LCD_TE (out), MFX_TSC_XN (out), MFX_TSC_XP (out), MFX_TSC_YN (out), MFX_TSC_YP (out), NRST (bidir)

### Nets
3V3: SB125.1 SB128.1
5V: SB127.1
BLGND: C92.1 C93.1 CN23.22(BL_GND) L3.2
GND: C110.2 CN23.26(GND) CN23.27(GND) CN23.30(SDI) H1.1 H2.1 L3.1 Q9.2(E) R93.1 R121.1 U35.6(GND) U35.11(A0) U35.13(GND)
VDD: SB123.1
VDD_BL: C92.2 C93.2 CN23.28(BL_VDD) L4.2 R104.2
VDD_LCD: CN23.24(VDD) R119.2 SB123.2 SB124.1 SB133.2
BL_CTRL: CN23.23(BL_CONTROL) Q9.3(C) R104.1
D0: CN23.6(PD1)
D1: CN23.7(PD2)
D2: CN23.8(PD3)
D3: CN23.9(PD4)
D4: CN23.10(PD5)
D5: CN23.11(PD6)
D6: CN23.12(PD7)
D7: CN23.13(PD8)
D8: CN23.14(PD10)
D9: CN23.15(PD11)
D10: CN23.16(PD12)
D11: CN23.17(PD13)
D12: CN23.18(PD14)
D13: CN23.19(PD15)
D14: CN23.20(PD16)
D15: CN23.21(PD17)
FMC_A22_LCD_RS: CN23.2(RS) ; port FMC_A22_LCD_RS
FMC_NE4_LCD_CSn: CN23.1(~{CS}) ; port FMC_NE4_LCD_CSn
FMC_NOE: CN23.4(~{RD}) ; port FMC_NOE
FMC_NWE: CN23.3(~{WR}/SCL) ; port FMC_NWE
I2C_SCL: SB138.2 U35.9(SCL) ; port I2C_SCL
I2C_SDA: SB141.2 U35.8(SDA) ; port I2C_SDA
LCD_CTP_INT: R119.1 SB137.2 U35.7(NIRQ) ; port LCD_CTP_INT
LCD_RESET: CN23.5(~{RESET}) ; port LCD_RESET
LCD_TE: SB143.2 ; port LCD_TE
MFX_TSC_XN: SB142.2 ; port MFX_TSC_XN
MFX_TSC_XP: SB136.2 ; port MFX_TSC_XP
MFX_TSC_YN: SB140.2 ; port MFX_TSC_YN
MFX_TSC_YP: SB139.2 ; port MFX_TSC_YP
NRST: R120.1 ; port NRST
PA8: R91.1 ; port LCD_BL_CTRL
TSC_XN: CN23.31(XL) SB131.2 SB142.1 SB143.1
TSC_XP: CN23.32(XR) SB129.2 SB136.1 SB137.1
TSC_YN: CN23.33(YD) SB132.2 SB140.1 SB141.1
TSC_YP: CN23.34(YU) SB130.2 SB138.1 SB139.1
NetC110_1: C110.1 SB133.1 U35.1(VDD)
NetCN23_25: CN23.25(VCI) SB124.2 SB125.2
NetL4_1: L4.1 SB127.2 SB128.2
NetQ9_1: Q9.1(B) R91.2 R93.2
NetR120_2: R120.2 U35.10(NRST)
NetR121_2: R121.2 U35.12(AUX)
NetSB129_1: SB129.1 U35.2(X+)
NetSB130_1: SB130.1 U35.3(Y+)
NetSB131_1: SB131.1 U35.4(X-)
NetSB132_1: SB132.1 U35.5(Y-)

Not connected (* = marked no-connect by the designer): CN23 29(SDO)*

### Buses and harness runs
bus D[0..15] = port D[0..15]

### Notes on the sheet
- Operating range: 2.5<VCI<3.3V
- (near SB123) Operating range: 1.65<VDD<3.3V
- (near CN23) LCD
- PD5
- PD4
- PG12
- MFX_IO12
- PE6
- PD14
- PD15
- PD0
- PD1
- PE7
- PE9
- PE10
- PE11
- PE8
- PE12
- PE13
- PE14
- PE15
- PD8
- PD9
- PD10
- LCD DATA bus should be routed in 50 ohm +/- 15%
- (near SB138) RESERVED FOR NEW LCD MODULE WITH INTEGRATED TCP
- TOUCH PANEL SEMTECH
- Operating range: 1.65<VDD<3.7V
- PA8
- (near R120) PG15
- PB10
- (near R120) PB11
- LIMITATIONS :
- LCD_TE exclusive with SMARTCARD_UART_RX
- See User Manual for more detail about muxing.
- Default I2C Address:0x90: 0b:1001.000x

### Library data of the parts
C92 = MCD-00014: Capacitor, MLCC, 10uF, 25V, X5R, 10%, 0805, T=0,85mm; Manufacturer_Part_Number: CC0805KRX5R8BB106; Manufacturer: YAGEO; Provided_By: Subcon; Initial_Board_Reference: MB1274
C93 C110 = MCD-00006: as C152 on sheet SDCARD
CN23 = MCD-01342: Socket, 17x2, 2.54mm, VR, TH, Height 8.51mm/2.64mm, Low insertion force for TFT LCD MB989; Part_Type: Connector; Manufacturer_Part_Number: SSW-117-21-x-D; Manufacturer: SAMTEC; Provided_By: Subcon; Initial_Board_Reference: MB1372
H1 H2 = MCD-00035: POSITION HOLE C6D3R5; Part_Type: Mechanical; Initial_Board_Reference: MB1274
L3 L4 = MCD-00047: SMD Chip ferrite bead, 600R@100MHz +/-25%, 350mA, 500mohm DC, 0603, T=0.8mm; Part_Type: Inductor; Manufacturer_Part_Number: FCM1608KF-601T03; Manufacturer: TAI-TECH; Provided_By: Subcon; Initial_Board_Reference: MB1274
Q9 = MCD-00073: as Q1 on sheet USB_TYPEC
R91 = MCD-00070: Resistor,1K,0603,1%,1/10W; Manufacturer_Part_Number: RC0603FR-071KL; Manufacturer: YAGEO; Provided_By: Subcon; Initial_Board_Reference: MB1274
R93 = MCD-00430: as R9 on sheet USB_TYPEC
R104 = MCD-00222: as R165 on sheet SDCARD
R119 = MCD-00220: as R174 on sheet SDCARD
R120 R121 = MCD-00056: as R134 on sheet PMOD_STMOD+
SB123-SB125 SB127-SB133 SB136-SB143 = MCD-00071: as SB93 on sheet SDCARD
U35 = MCD-01952: Multitouch 4-wire Resistive Touchscreen Controller with 15kV ESD Protection; Part_Type: IC; Manufacturer_Part_Number: SX8651IWLTRT; Manufacturer: SEMTECH; ECCN_US: tbd; Provided_By: SUBCO

## Sheet ST_LINK_V3E.SchDoc: STLINK V3E
size A3; Date: Not used; ApprovedBy: Not used; CheckedBy: Not used; Author: Not used; CompanyName: STMicroelectronics; DrawnBy: Not used; Engineer: Not used; Organization: Not used; Address1: Not used; Address2: Not used; Address3: Not used; Address4: Not used; DocumentNumber: 23; Revision: Not used; SheetNumber: 23; SheetTotal: 24
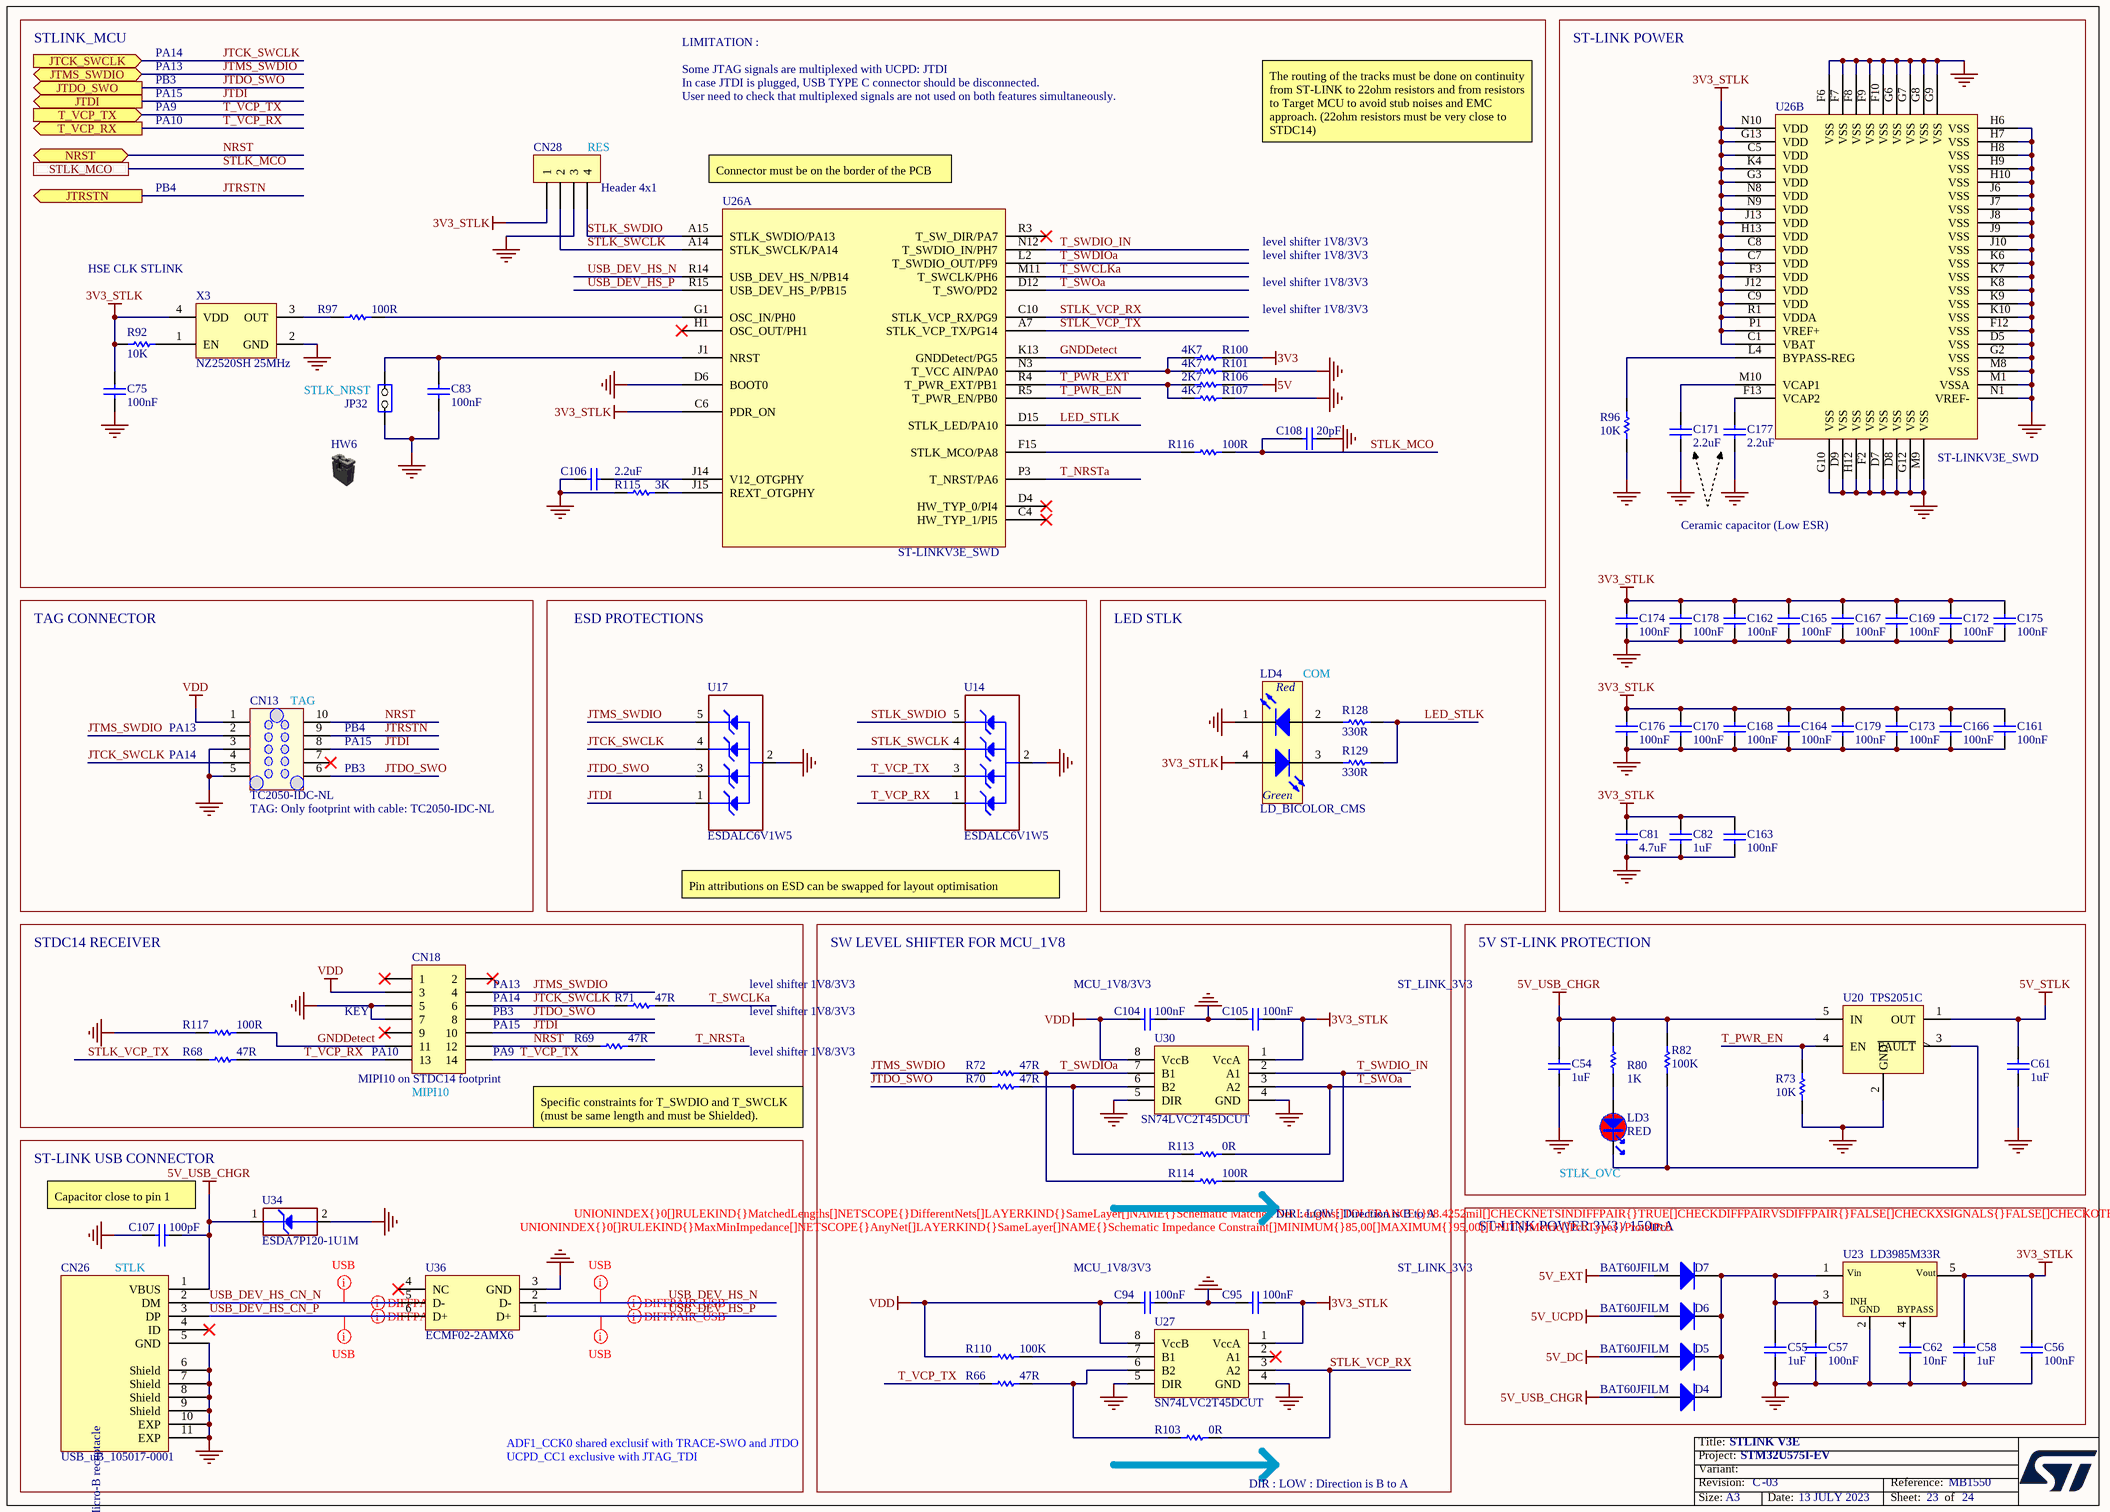
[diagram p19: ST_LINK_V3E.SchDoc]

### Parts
C54  value 1uF  [C0402]
C55  value 1uF  [C0402]
C56  value 100nF  [C0402]
C57  value 100nF  [C0402]
C58  value 1uF  [C0402]
C61  value 1uF  [C0402]
C62  value 10nF  [C0402]  (hidden comment: Capacitor)
C75  value 100nF  [C0402]
C81  value 4.7uF  [C0603]
C82  value 1uF  [C0402]
C83  value 100nF  [C0402]
C94  value 100nF  [C0402]
C95  value 100nF  [C0402]
C104  value 100nF  [C0402]
C105  value 100nF  [C0402]
C106  value 2.2uF  [C0603]
C107  value 100pF  [C0402]  (hidden comment: Capacitor)
C108  value 20pF  [C0402]
C161  value 100nF  [C0402]
C162  value 100nF  [C0402]
C163  value 100nF  [C0402]
C164  value 100nF  [C0402]
C165  value 100nF  [C0402]
C166  value 100nF  [C0402]
C167  value 100nF  [C0402]
C168  value 100nF  [C0402]
C169  value 100nF  [C0402]
C170  value 100nF  [C0402]
C171  value 2.2uF  [C0402]
C172  value 100nF  [C0402]
C173  value 100nF  [C0402]
C174  value 100nF  [C0402]
C175  value 100nF  [C0402]
C176  value 100nF  [C0402]
C177  value 2.2uF  [C0402]
C178  value 100nF  [C0402]
C179  value 100nF  [C0402]
CN13  value TC2050-IDC-NL  [CON_TAG-C_TC2050-IDC-NL]
CN18  value MIPI10 on STDC14 footprint  [CON_STDC14_Receiver_MEDIUM_WITH_MIPI10_3D]
CN26  value USB_uB_105017-0001  [CON_USBMICROB_MOLEX_105017-0001_H2P90]  (hidden comment: USB_uB_105017.0001)
CN28  Header 4x1  [CON_SAMTEC_TSW-104-07-G-S]
D4  BAT60JFILM  [DIO_SOD323]
D5  BAT60JFILM  [DIO_SOD323]
D6  BAT60JFILM  [DIO_SOD323]
D7  BAT60JFILM  [DIO_SOD323]
HW6  Shunt Black 2.54mm  (value not drawn)  (mechanical)
JP32  Jumper_Header 2x1  [CON_SAMTEC_TSW-102-07-G-S]  (value not drawn)
LD3  value RED  [LED_0603_VISHAY_VLMS1300-GS08_RED_1A2K_H0P8]
LD4  LD_BICOLOR_CMS  [LED_BI-GR_HSMF-A201-A00J1]
R66  value 47R  [R0402]
R68  value 47R  [R0402]
R69  value 47R  [R0402]
R70  value 47R  [R0402]
R71  value 47R  [R0402]
R72  value 47R  [R0402]
R73  value 10K  [R0603]
R80  value 1K  [R0603]
R82  value 100K  [R0603]
R92  value 10K  [R0603]
R96  value 10K  [R0603]
R97  value 100R  [R0402]
R100  value 4K7  [R0402]
R101  value 4K7  [R0402]
R103  value 0R  [R0402]
R106  value 2K7  [R0402]
R107  value 4K7  [R0402]
R110  value 100K  [R0603]
R113  value 0R  [R0402]
R114  value 100R  [R0402]
R115  value 3K  [R0402]
R116  value 100R  [R0402]
R117  value 100R  [R0402]
R128  value 330R  [R0402]
R129  value 330R  [R0402]
U14  ESDALC6V1W5  [ESD_SOT323-5L]
U17  ESDALC6V1W5  [ESD_SOT323-5L]
U20  TPS2051C  [MOS_SOT23-5L]
U23  LD3985M33R  [REG_SOT23-5L]
U26  value ST-LINKV3E_SWD  [ICC_UFBGA201_176+25_10X10_P065]  (parts A,B of 2)
U27  SN74LVC2T45DCUT  [ICC_VSSOP8_DCU_R-PDSO-G8_2X2P30_P050]
U30  SN74LVC2T45DCUT  [ICC_VSSOP8_DCU_R-PDSO-G8_2X2P30_P050]
U34  value ESDA7P120-1U1M  [ESD_QFN1610_2N_1K_2A]
U36  value ECMF02-2AMX6  [ESD_QFN-6L_1P7X1P5_P050]
X3  value NZ2520SH 25MHz  [OSC_NDK_NZ2520SB_4P]

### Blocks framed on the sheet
STLINK_MCU: C75 C83 C106 C108 CN28 HW6 JP32 R92 R97 R100 R101 R106 R107 R115 R116 U26 X3
ST-LINK POWER: C81 C82 C161-C179 R96 U26
TAG CONNECTOR: CN13
ESD PROTECTIONS: U14 U17
LED STLK: LD4 R128 R129
STDC14 RECEIVER: CN18 R68 R69 R71 R117
SW LEVEL SHIFTER FOR MCU_1V8: C94 C95 C104 C105 R66 R70 R72 R103 R110 R113 R114 U27 U30
5V ST-LINK PROTECTION: C54 C61 LD3 R73 R80 R82 U20
ST-LINK USB CONNECTOR: C107 CN26 U34 U36
ST-LINK POWER 3V3 / 150mA: C55-C58 C62 D4-D7 U23

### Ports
JTCK_SWCLK (in), JTDI (out), JTDO_SWO (out), JTMS_SWDIO (bidir), JTRSTN (out), NRST (bidir), STLK_MCO, T_VCP_RX (out), T_VCP_TX (in)

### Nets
3V3: R100.2
3V3_STLK: C56.2 C58.1 C75.1 C81.2 C82.1 C95.2 C105.2 C161.1 C162.1 C163.1 C164.1 C165.1 C166.1 C167.1 C168.1 C169.1 C170.1 C172.1 C173.1 C174.1 C175.1 C176.1 C178.1 C179.1 CN28.1 LD4.4(YellowGreen_anode) R92.2 U23.5(Vout) U26.C1(VBAT) U26.C5(VDD) U26.C6(PDR_ON) U26.C7(VDD) U26.C8(VDD) U26.C9(VDD) U26.F3(VDD) U26.G3(VDD) U26.G13(VDD) U26.H13(VDD) U26.J12(VDD) U26.J13(VDD) U26.K4(VDD) U26.N8(VDD) U26.N9(VDD) U26.N10(VDD) U26.P1(VREF+) U26.R1(VDDA) U27.1(VccA) U30.1(VccA) X3.4(VDD)
5V: R106.1
5V_DC: D5.1(A)
5V_EXT: D7.1(A)
5V_STLK: C61.1 U20.1(OUT)
5V_UCPD: D6.1(A)
5V_USB_CHGR: C54.1 C107.2 CN26.1(VBUS) D4.1(A) R80.2 R82.2 U20.5(IN) U34.1(IO1)
GND: C54.2 C55.2 C56.1 C57.1 C58.2 C61.2 C62.1 C75.2 C81.1 C82.2 C83.2 C94.2 C95.1 C104.2 C105.1 C106.1 C107.1 C108.1 C161.2 C162.2 C163.2 C164.2 C165.2 C166.2 C167.2 C168.2 C169.2 C170.2 C171.1 C172.2 C173.2 C174.2 C175.2 C176.2 C177.1 C178.2 C179.2 CN13.3 CN13.5 CN18.5 CN18.7 CN26.5(GND) CN26.6(Shield) CN26.7(Shield) CN26.8(Shield) CN26.9(Shield) CN26.10(EXP) CN26.11(EXP) CN28.3 JP32.1(COMMON) LD4.1(RED_cathode) R73.1 R96.1 R101.2 R107.1 R115.1 R117.1 U14.2(GND) U17.2(GND) U20.2(GND) U23.2(GND) U26.D5(VSS) U26.D6(BOOT0) U26.D7(VSS) U26.D8(VSS) U26.D9(VSS) U26.F2(VSS) U26.F6(VSS) U26.F7(VSS) U26.F8(VSS) U26.F9(VSS) U26.F10(VSS) U26.F12(VSS) U26.G2(VSS) U26.G6(VSS) U26.G7(VSS) U26.G8(VSS) U26.G9(VSS) U26.G10(VSS) U26.G12(VSS) U26.H6(VSS) U26.H7(VSS) U26.H8(VSS) U26.H9(VSS) U26.H10(VSS) U26.H12(VSS) U26.J6(VSS) U26.J7(VSS) U26.J8(VSS) U26.J9(VSS) U26.J10(VSS) U26.K6(VSS) U26.K7(VSS) U26.K8(VSS) U26.K9(VSS) U26.K10(VSS) U26.M1(VSSA) U26.M8(VSS) U26.M9(VSS) U26.N1(VREF-) U27.4(GND) U27.5(DIR) U30.4(GND) U30.5(DIR) U34.2(GND) U36.3(GND) X3.2(GND)
VDD: C94.1 C104.1 CN13.1 CN18.3 R110.2 U27.8(VccB) U30.8(VccB)
GNDDetect: CN18.11 R117.2 U26.K13(GNDDetect/PG5)
JTCK_SWCLK: CN13.4 CN18.6 R71.1 U17.4(IO3) ; port JTCK_SWCLK
JTDI: CN13.8 CN18.10 U17.1(IO1) ; port JTDI
JTDO_SWO: CN13.6 CN18.8 R70.1 U17.3(IO2) ; port JTDO_SWO
JTMS_SWDIO: CN13.2 CN18.4 R72.1 U17.5(IO4) ; port JTMS_SWDIO
JTRSTN: CN13.9 ; port JTRSTN
LED_STLK: R128.2 R129.2 U26.D15(STLK_LED/PA10)
NRST: CN13.10 CN18.12 R69.1 ; port NRST
STLK_MCO: C108.2 R116.2 ; port STLK_MCO
STLK_SWCLK: CN28.2 U14.4(IO3) U26.A14(STLK_SWCLK/PA14)
STLK_SWDIO: CN28.4 U14.5(IO4) U26.A15(STLK_SWDIO/PA13)
STLK_VCP_RX: R103.2 U26.C10(STLK_VCP_RX/PG9) U27.3(A2)
STLK_VCP_TX: R68.1 U26.A7(STLK_VCP_TX/PG14)
T_NRSTa: R69.2 U26.P3(T_NRST/PA6)
T_PWR_EN: R73.2 U20.4(EN) U26.R5(T_PWR_EN/PB0)
T_PWR_EXT: R106.2 R107.2 U26.R4(T_PWR_EXT/PB1)
T_SWCLKa: R71.2 U26.M11(T_SWCLK/PH6)
T_SWDIO_IN: R114.2 U26.N12(T_SWDIO_IN/PH7) U30.2(A1)
T_SWDIOa: R72.2 R114.1 U26.L2(T_SWDIO_OUT/PF9) U30.7(B1)
T_SWOa: R113.2 U26.D12(T_SWO/PD2) U30.3(A2)
T_VCP_RX: CN18.13 R68.2 U14.1(IO1) ; port T_VCP_RX  [project net PA10]
T_VCP_TX: CN18.14 R66.1 U14.3(IO2) ; port T_VCP_TX  [project net PA9]
USB_DEV_HS_CN_N: CN26.2(DM) U36.5(D-)
USB_DEV_HS_CN_P: CN26.3(DP) U36.6(D+)
USB_DEV_HS_N: U26.R14(USB_DEV_HS_N/PB14) U36.2(D-)
USB_DEV_HS_P: U26.R15(USB_DEV_HS_P/PB15) U36.1(D+)
NetC55_1: C55.1 C57.2 D4.2(K) D5.2(K) D6.2(K) D7.2(K) U23.1(Vin) U23.3(CE)
NetC62_2: C62.2 U23.4(BYPASS)
NetC83_1: C83.1 JP32.2(NO) U26.J1(NRST)
NetC106_2: C106.2 U26.J14(V12_OTGPHY)
NetC171_2: C171.2 U26.M10(VCAP1)
NetC177_2: C177.2 U26.F13(VCAP2)
NetLD3_1: LD3.1 R80.1
NetLD3_2: LD3.2 R82.1 U20.3(~{FAULT})
NetLD4_2: LD4.2(Red_anode) R128.1
NetLD4_3: LD4.3(YellowGreen_cathode) R129.1
NetR66_2: R66.2 R103.1 U27.6(B2)
NetR70_2: R70.2 R113.1 U30.6(B2)
NetR92_1: R92.1 X3.1(EN)
NetR96_2: R96.2 U26.L4(BYPASS-REG)
NetR97_1: R97.1 X3.3(OUT)
NetR97_2: R97.2 U26.G1(OSC_IN/PH0)
NetR100_1: R100.1 R101.1 U26.N3(T_VCC_AIN/PA0)
NetR110_1: R110.1 U27.7(B1)
NetR115_2: R115.2 U26.J15(REXT_OTGPHY)
NetR116_1: R116.1 U26.F15(STLK_MCO/PA8)

Not connected (* = marked no-connect by the designer): CN13 7*; CN18 1* 2* 9*; CN26 4(ID)*; U26 C4(HW_TYP_1/PI5)* D4(HW_TYP_0/PI4)* H1(OSC_OUT/PH1)* R3(T_SW_DIR/PA7)*; U27 2(A1)*; U36 4(NC)*

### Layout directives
differential pair; rule Impedance Constraint [Min = 85.00    Max = 95.00    ]: USB_DEV_HS_CN_N, USB_DEV_HS_CN_P, USB_DEV_HS_N, USB_DEV_HS_P
rule Undefined; rule Matched Net Lengths [Tolerance = 2.5mm]; rule Impedance Constraint [Min = 85.00    Max = 95.00    ]: USB_DEV_HS_N
rule Undefined; rule Matched Net Lengths [Tolerance = 0.2mm]; rule Impedance Constraint [Min = 85.00    Max = 95.00    ]: USB_DEV_HS_CN_N, USB_DEV_HS_CN_P, USB_DEV_HS_P

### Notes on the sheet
- PA14
- PA13
- PB3
- PA15
- PA9
- LIMITATION :
  Some JTAG signals are multiplexed with UCPD: JTDI
  In case JTDI is plugged, USB TYPE C connector should be disconnected.
  User need to check that multiplexed signals are not used on both features simultaneously.
- PA10
- (near CN28) RES
- Connector must be on the border of the PCB
- The routing of the tracks must be done on continuity from ST-LINK to 22ohm resistors and from resistors to Target MCU to avoid stub noises and EMC approach. (22ohm resistors must be very close to STDC14)
- PB4
- level shifter 1V8/3V3
- HSE CLK STLINK
- (near JP32) STLK_NRST
- Ceramic capacitor (Low ESR)
- (near CN13) TAG
- COM
- (near CN13) PA15
- (near CN13) PB3
- (near CN13) PB4
- (near CN13) TAG: Only footprint with cable: TC2050-IDC-NL
- Pin attributions on ESD can be swapped for layout optimisation
- (near CN18) PA13
- (near R71) level shifter 1V8/3V3
- MCU_1V8/3V3
- ST_LINK_3V3
- (near CN18) KEY
- (near CN18) PA10
- (near CN18) PA14
- (near CN18) PB3
- (near CN18) PA15
- (near CN18) PA9
- (near R69) level shifter 1V8/3V3
- (near CN18) MIPI10
- (near R69) Specific constraints for T_SWDIO and T_SWCLK (must be same length and must be Shielded).
- (near LD3) STLK_OVC
- (near C107) Capacitor close to pin 1
- (near R114) DIR : LOW : Direction is B to A
- STLK
- ADF1_CCK0 shared exclusif with TRACE-SWO and JTDO
- UCPD_CC1 exclusive with JTAG_TDI
- (near R103) DIR : LOW : Direction is B to A

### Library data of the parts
C54 C55 C58 C61 C82 = MCD-00095: Capacitor, MLCC, 1uF, 25V, X5R, 10%, 0402, T=0,5mm; Manufacturer_Part_Number: GRM155R61E105KA12; Manufacturer: MURATA; Alternate_Manufacturer_Part_Number: GRM155R60J105KE19; ECCN_US: EAR99; ECCN_EU: NEC; Provided_By: SUBCO
C56 C57 C75 C83 C94 C95 C104 C105 C161-C170 C172-C176 C178 C179 = MCD-00006: as C152 on sheet SDCARD
C62 = MCD-00011: Capacitor, MLCC, 10nF, 16V, X7R, 10%, 0402, T=0.5mm; Manufacturer_Part_Number: CC0402KRX7R7BB103; Manufacturer: YAGEO; Provided_By: Subcon; Initial_Board_Reference: MB1274
C81 = MCD-00009: Capacitor, MLCC, 4.7uF, 16V, X5R, 10%, 0603, T=0.8mm; Manufacturer_Part_Number: CC0603KRX5R7BB475; Manufacturer: YAGEO; Provided_By: SUBCO; ECCN_US: EAR99; ECCN_EU: NEC
C106 = MCD-00012: Capacitor, MLCC, 2.2uF, 10V, X5R, 10%, 0603, T=0,8mm; Manufacturer_Part_Number: CC0603KRX5R6BB225; Manufacturer: YAGEO; Alternate_Manufacturer_Part_Number: C0603C225K8PACTU; Alternate_Manufacturer: KEMET; BMS_Part_Number: 9142010; Provided_By: SUBCO; ECCN_US: EAR99; ECCN_EU: NEC
C107 = MCD-00205: Capacitor, MLCC, 100pF, 50V, NPO, 5%, 0402, T=0,5mm; Manufacturer_Part_Number: CC0402JRNPO9BN101; Manufacturer: YAGEO; Provided_By: Subcon; Initial_Board_Reference: MB1361
C108 = MCD-00016: Capacitor, MLCC, 20pF, 50V, NPO, 5%, 0402, T=0,5mm; Manufacturer_Part_Number: CC0402JRNPO9BN200; Manufacturer: YAGEO; Provided_By: SUBCO; ECCN_US: EAR99; ECCN_EU: NEC
C171 C177 = MCD-01823: Capacitor,MLCC,2.2uF,6V3,X5R,10%,0402,T=0.5; Manufacturer_Part_Number: GRM155R60J225KE95D; Manufacturer: MURATA; ECCN_US: EAR99; ECCN_EU: NEC; Provided_By: SUBCO
CN13 = MCD-00031: Tag_Connector Header, 10x2, No legs; Manufacturer_Part_Number: TC2050-IDC-NL-FP; Manufacturer: TAG-CONNECT LLC; Provided_By: Subcon; Initial_Board_Reference: MB1274
CN18 = MCD-01226: Header 5x2, 1.27mm, Dual row, Straight, Surface mount, vertical male connector. 3.05mm lead. Mates with FFSD connector. Footprint compatible with FTSH-107-01-L-DV,-K,-A,-P,-ES (STDC14 MEDIUM); Manufacturer_Part_Number: FTSH-105-01-L-DV-K; Manufacturer: SAMTEC; Alternate_Manufacturer_Part_Number: P127B-2x05MGF-079-1A; Alternate_Manufacturer: JIUBABA; Provided_By: SUBCO
CN26 = MCD-00028: USB-MICRO-B, 0.65mm, RA, SMT, Bottom Mount,; Manufacturer_Part_Number: 1050170001; Manufacturer: MOLEX; Part_Type: Connector; Provided_By: Subcon; Initial_Board_Reference: MB1274
CN28 = MCD-00029: Header, 4x1, 2,54mm, VR, TH, Height 5.84mm/2.54mm; Manufacturer_Part_Number: TSW-104-07-x-S; Manufacturer: SAMTEC; Part_Type: Connector; Provided_By: Subcon; Initial_Board_Reference: MB1274
D4-D7 = MCD-00034: Manufacturer: STMICROELECTRONICS; Part_Type: Diode; BMS_Part_Number: 9151097; Provided_By: Subcon; Initial_Board_Reference: MB1274
HW6 = MCD-00043: as HW9 on sheet USB_TYPEC
JP32 = MCD-00045: Header, 2x1, 2,54mm, VR, TH, Height 5.84mm/2.54mm; Part_Type: Connector; Manufacturer_Part_Number: TSW-102-07-x-S; Manufacturer: SAMTEC; Value: Shunt not fitted; Provided_By: Subcon; Initial_Board_Reference: MB1274; Remark: 3D KO: BZ: 40098
LD3 = MCD-00587: LED Red, 0603 SMD, 2V Forward Voltage; Part_Type: Display; Manufacturer_Part_Number: VLMS1300-GS08; Manufacturer: VISHAY; Alternate_Manufacturer_Part_Number: LS Q976-NR-1; Alternate_Manufacturer: OSRAM OPTO SEMICONDUCTORS; Provided_By: Subcon; Initial_Board_Reference: MB1331
LD4 = MCD-02402: LED Bicolor; Part_Type: Display; Part_Preference: Alternate; Manufacturer: EVERLIGHT; Manufacturer_Part_Number: 67-22SURSYGC/S530-A2/TR8; Full_Alternate_Internal_Part_Number: MCD-00051, MCD-02631; Alternate_EMS: C; ShowFields: YES; ID: 4508
R66 R68-R72 = MCD-00481: Resistor,47R,0402,1%,1/16W; Manufacturer_Part_Number: RC0402FR-0747RL; Manufacturer: YAGEO; Provided_By: SUBCO; ECCN_US: EAR99; ECCN_EU: NEC
R73 R92 R96 = MCD-00220: as R174 on sheet SDCARD
R80 = MCD-00070: as R91 on sheet LCD_TFT_320x240
R82 R110 = MCD-00223: as R16 on sheet PMOD_STMOD+
R97 R114 R116 R117 = MCD-00067: Resistor,100R,0402,1%,1/16W; Manufacturer_Part_Number: RC0402FR-07100RL; Manufacturer: YAGEO; ECCN_US: EAR99; ECCN_EU: NEC; Provided_By: SUBCO
R100 R101 R107 = MCD-00065: Resistor,4K7,0402,1%,1/16W; Manufacturer_Part_Number: RC0402FR-074K7L; Manufacturer: YAGEO; Alternate_Manufacturer_Part_Number: RT0402FRE074K7L; Provided_By: SUBCO; ECCN_US: EAR99; ECCN_EU: NEC
R103 R113 = MCD-00052: Resistor,0R,0402,5%,1/16W; Manufacturer_Part_Number: RC0402JR-070RL; Manufacturer: YAGEO; Provided_By: Subcon; Initial_Board_Reference: MB1274
R106 = MCD-00055: Resistor,2K7,0402,1%,1/16W; Manufacturer_Part_Number: RC0402FR-072K7L; Manufacturer: YAGEO; Provided_By: SUBCO; ECCN_US: EAR99; ECCN_EU: NEC
R115 = MCD-00185: Resistor,3K,0402,1%,1/16W; Manufacturer_Part_Number: RC0402FR-073KL; Manufacturer: YAGEO; Provided_By: SUBCO; ECCN_US: EAR99; ECCN_EU: NEC
R128 R129 = MCD-00062: Resistor,330R,0402,1%,1/16W; Manufacturer_Part_Number: RC0402FR-07330RL; Manufacturer: YAGEO; Provided_By: SUBCO; ECCN_US: EAR99; ECCN_EU: NEC
U14 U17 = MCD-00136: Dual Transil array for ESD protection; Part_Type: Diode; Manufacturer: STMICROELECTRONICS; BMS_Part_Number: 9151112; Provided_By: Subcon; Initial_Board_Reference: MB1262
U20 = MCD-02309: Power Switch, 5V, 0.85A, RDSon 130mOhm max, with active High enable pin and resistor discharge; Part_Type: IC; Part_Preference: Recommended; Manufacturer: TEXAS INSTRUMENTS; Manufacturer_Part_Number: TPS2051CDBVT
U23 = MCD-00086: Ultra low drop-low noise BiCMOS voltage, regulators low ESR capacitors compatible; Manufacturer: STMICROELECTRONICS; Part_Type: IC; BMS_Part_Number: 9176161; Provided_By: Subcon; Initial_Board_Reference: MB1274
U26 = MCD-00596: STM32F723IEK  (STM32F7) BGA176; Part_Type: IC; Manufacturer_Part_Number: STM32F723IEK6; Manufacturer: STMICROELECTRONICS; BMS_Part_Number: 9175300; Provided_By: SUBCO with ST control; ECCN_US: 3A991A2; ECCN_EU: NEC
U27 U30 = MCD-00264: Dual bit dual supply bus transceiver; Part_Type: IC; Manufacturer: TEXAS INSTRUMENTS; Provided_By: Subcon; Initial_Board_Reference: MB1319
U34 = MCD-01026: High power transient voltage suppressor; Part_Type: Diode; Manufacturer: STMICROELECTRONICS; BMS_Part_Number: 9179046; Provided_By: SUBCO with ST control; ECCN_US: EAR99; ECCN_EU: NEC
U36 = MCD-00649: Common mode filter with ESD protection for USB 2.0 interface; Part_Type: Diode; Manufacturer: STMICROELECTRONICS; BMS_Part_Number: 9151138; Provided_By: SUBCO with ST control; ECCN_US: EAR99; ECCN_EU: NEC
X3 = MCD-00597: Oscillator 25Mhz, +-50ppm, Vcc:3.3V typ, square wave: [0.1Vcc;0.9Vcc], Enable pin, SMD; Part_Type: Crystal_Osc; Manufacturer_Part_Number: NZ2520SH 25MHz END4869C; Manufacturer: NDK; Alternate_Manufacturer_Part_Number: NZ2520SB 25MHz END4869B; BMS_Part_Number: 9157050; Provided_By: SUBCO; ECCN_US: EAR99; ECCN_EU: NEC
